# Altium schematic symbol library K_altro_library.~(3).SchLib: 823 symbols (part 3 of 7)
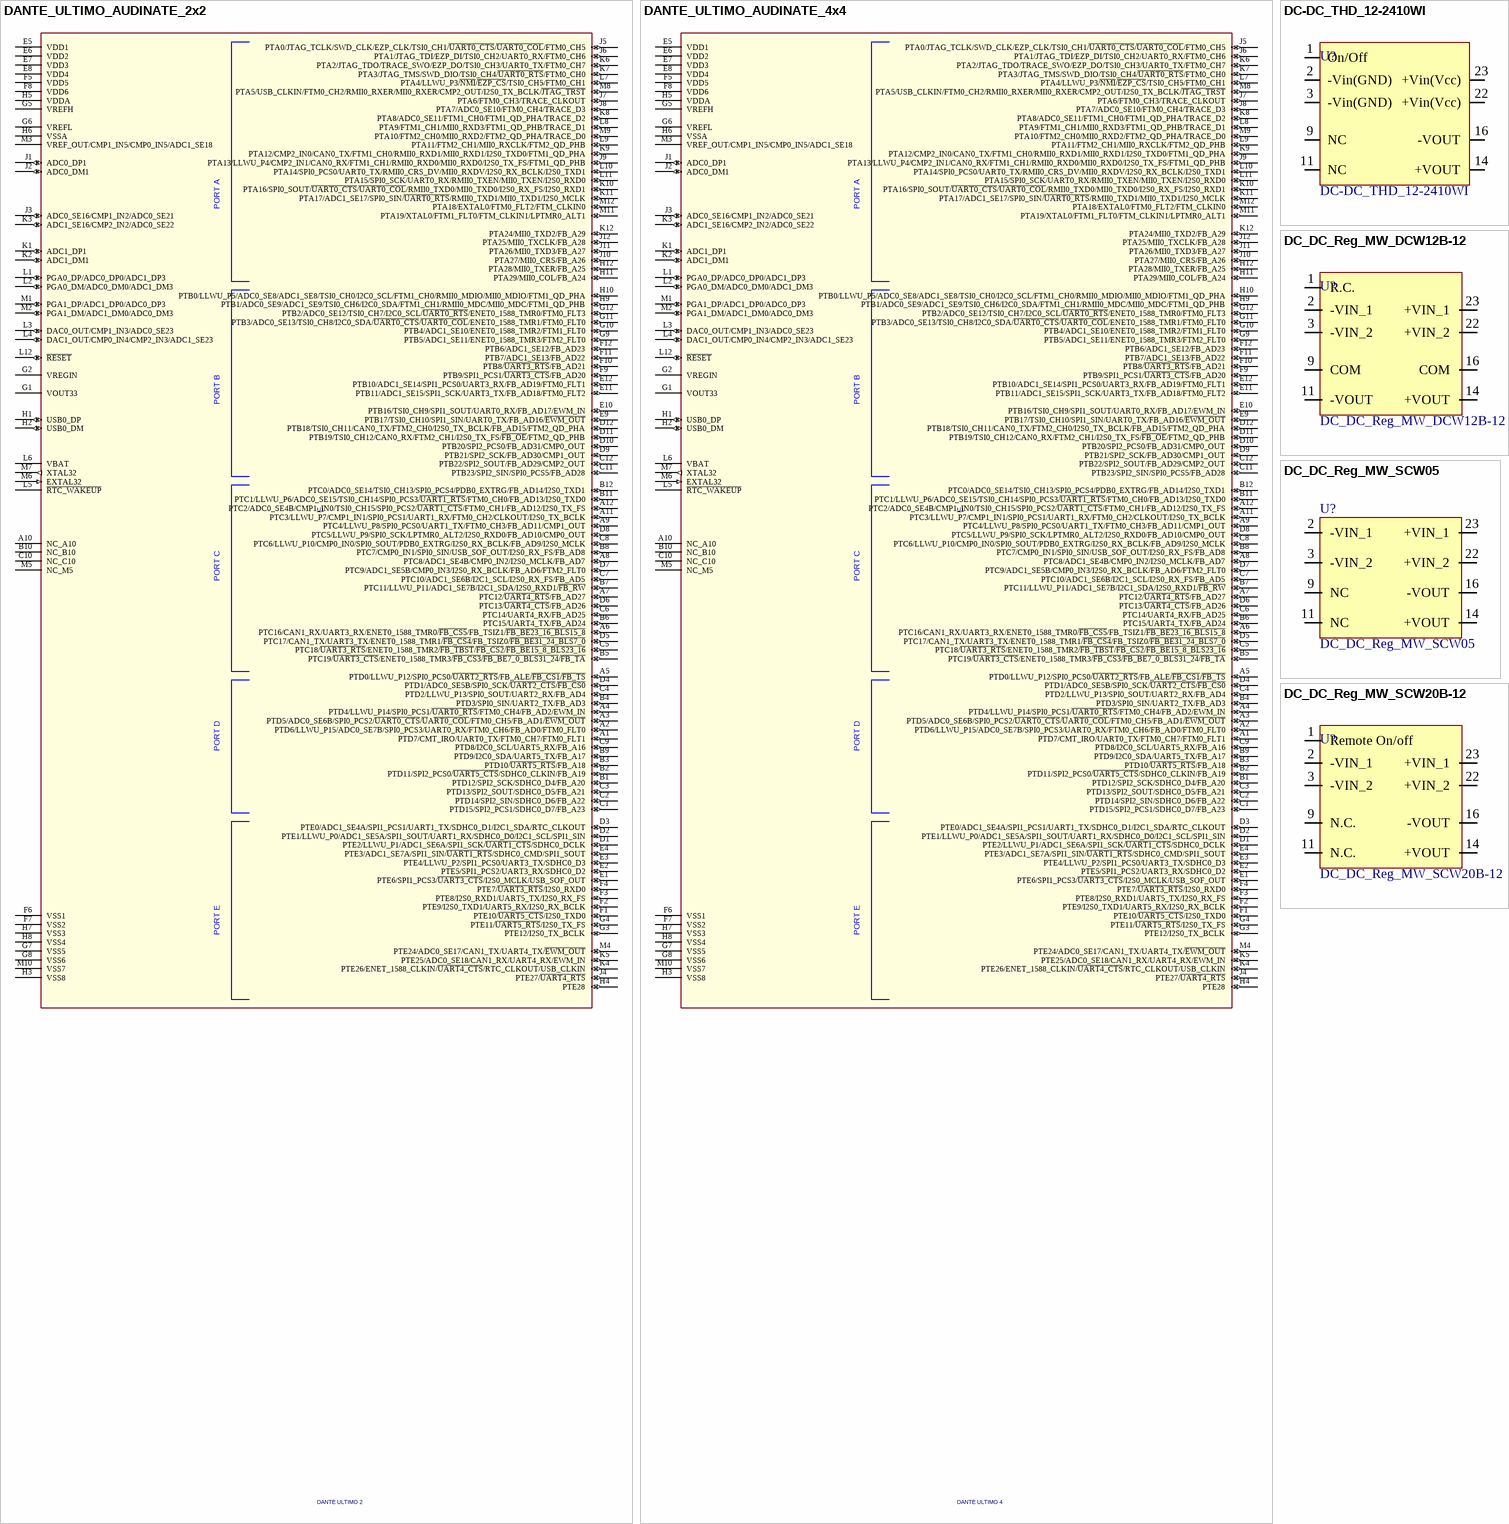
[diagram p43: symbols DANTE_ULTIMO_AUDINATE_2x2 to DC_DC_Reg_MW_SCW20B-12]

## DANTE_ULTIMO_AUDINATE_4x4
designator U1, comment DANTE ULTIMO 4
AUDINATE DANTE ULTIMO 4; Costo: 17; HPcode: 'ICULTIMO4x4 da codificare!; Aggiornato: S; ContoLavoro: 1
footprint FBGA144_mod (144-Ball FineLine Ball Grid Array (FBGA144))
pins: A1 PTD7/CMT_IRO/UART0_TX/FTM0_CH7/FTM0_FLT1 (io), A2 PTD6/LLWU_P15/ADC0_SE7B/SPI0_PCS3/UART0_RX/FTM0_CH6/FB_AD0/FTM0_FLT0 (io), A3 PTD5/ADC0_SE6B/SPI0_PCS2/~{UART0_CTS}/~{U}A~{RT0_COL}/FTM0_CH5/FB_AD1/~{EWM_OUT} (io), A4 PTD4/LLWU_P14/SPI0_PCS1/~{UART0_RTS}/FTM0_CH4/FB_AD2/EWM_IN (io), A5 PTD0/LLWU_P12/SPI0_PCS0/~{UART2_RTS}/FB_ALE/~{FB_CS1}/~{FB_TS} (io), A6 PTC16/CAN1_RX/UART3_RX/ENET0_1588_TMR0/~{FB_CS5}/FB_TSIZ1/~{FB_BE23_16_BLS15_8} (io), A7 PTC12/~{UART4_RTS}/FB_AD27 (io), A8 PTC8/ADC1_SE4B/CMP0_IN2/I2S0_MCLK/FB_AD7 (io), A9 PTC4/LLWU_P8/SPI0_PCS0/UART1_TX/FTM0_CH3/FB_AD11/CMP1_OUT (io), A10 NC_A10, A11 PTC3/LLWU_P7/CMP1_IN1/SPI0_PCS1/UART1_RX/FTM0_CH2/CLKOUT/I2S0_TX_BCLK (io), A12 PTC2/ADC0_SE4B/CMP1_IN0/TSI0_CH15/SPI0_PCS2/~{UART1_CTS}/FTM0_CH1/FB_AD12/I2S0_TX_FS (io), B1 PTD12/SPI2_SCK/SDHC0_D4/FB_A20 (io), B2 PTD11/SPI2_PCS0/~{UART5_CTS}/SDHC0_CLKIN/FB_A19 (io), B3 PTD10/~{UART5_RTS}/FB_A18 (io), B4 PTD3/SPI0_SIN/UART2_TX/FB_AD3 (io), B5 PTC19/~{UART3_CTS}/ENET0_1588_TMR3/~{FB_CS3}/~{FB_BE7_0_BLS31_24}/~{FB_TA} (io), B6 PTC15/UART4_TX/FB_AD24 (io), B7 PTC11/LLWU_P11/ADC1_SE7B/I2C1_SDA/I2S0_RXD1/~{FB_RW} (io), B8 PTC7/CMP0_IN1/SPI0_SIN/USB_SOF_OUT/I2S0_RX_FS/FB_AD8 (io), B9 PTD9/I2C0_SDA/UART5_TX/FB_A17 (io), B10 NC_B10, B11 PTC1/LLWU_P6/ADC0_SE15/TSI0_CH14/SPI0_PCS3/~{UART1_RTS}/FTM0_CH0/FB_AD13/I2S0_TXD0 (io), B12 PTC0/ADC0_SE14/TSI0_CH13/SPI0_PCS4/PDB0_EXTRG/FB_AD14/I2S0_TXD1 (io), C1 PTD15/SPI2_PCS1/SDHC0_D7/FB_A23 (io), C2 PTD14/SPI2_SIN/SDHC0_D6/FB_A22 (io), C3 PTD13/SPI2_SOUT/SDHC0_D5/FB_A21 (io), C4 PTD2/LLWU_P13/SPI0_SOUT/UART2_RX/FB_AD4 (io), C5 PTC18/~{UART3_RTS}/ENET0_1588_TMR2/~{FB_TBST}/~{FB_CS2}/~{FB_BE15_8_BLS23_16} (io), C6 PTC14/UART4_RX/FB_AD25 (io), C7 PTC10/ADC1_SE6B/I2C1_SCL/I2S0_RX_FS/FB_AD5 (io), C8 PTC6/LLWU_P10/CMP0_IN0/SPI0_SOUT/PDB0_EXTRG/I2S0_RX_BCLK/FB_AD9/I2S0_MCLK (io), C9 PTD8/I2C0_SCL/UART5_RX/FB_A16 (io), C10 NC_C10, C11 PTB23/SPI2_SIN/SPI0_PCS5/FB_AD28 (io), C12 PTB22/SPI2_SOUT/FB_AD29/CMP2_OUT (io), D1 PTE2/LLWU_P1/ADC1_SE6A/SPI1_SCK/~{UART1_CTS}/SDHC0_DCLK (io), D2 PTE1/LLWU_P0/ADC1_SE5A/SPI1_SOUT/UART1_RX/SDHC0_D0/I2C1_SCL/SPI1_SIN (io), D3 PTE0/ADC1_SE4A/SPI1_PCS1/UART1_TX/SDHC0_D1/I2C1_SDA/RTC_CLKOUT (io), D4 PTD1/ADC0_SE5B/SPI0_SCK/~{UART2_CTS}/~{FB_CS0} (io), D5 PTC17/CAN1_TX/UART3_TX/ENET0_1588_TMR1/~{FB_CS4}/FB_TSIZ0/~{FB_BE31_24_BLS7_0} (io), D6 PTC13/~{UART4_CTS}/FB_AD26 (io), D7 PTC9/ADC1_SE5B/CMP0_IN3/I2S0_RX_BCLK/FB_AD6/FTM2_FLT0 (io), D8 PTC5/LLWU_P9/SPI0_SCK/LPTMR0_ALT2/I2S0_RXD0/FB_AD10/CMP0_OUT (io), D9 PTB21/SPI2_SCK/FB_AD30/CMP1_OUT (io), D10 PTB20/SPI2_PCS0/FB_AD31/CMP0_OUT (io), D11 PTB19/TSI0_CH12/CAN0_RX/FTM2_CH1/I2S0_TX_FS/~{FB_OE}/FTM2_QD_PHB (io), D12 PTB18/TSI0_CH11/CAN0_TX/FTM2_CH0/I2S0_TX_BCLK/FB_AD15/FTM2_QD_PHA (io), E1 PTE6/SPI1_PCS3/~{UART3_CTS}/I2S0_MCLK/USB_SOF_OUT (io), E2 PTE5/SPI1_PCS2/UART3_RX/SDHC0_D2 (io), E3 PTE4/LLWU_P2/SPI1_PCS0/UART3_TX/SDHC0_D3 (io), E4 PTE3/ADC1_SE7A/SPI1_SIN/~{UART1_RTS}/SDHC0_CMD/SPI1_SOUT (io), E5 VDD1 (power), E6 VDD2 (power), E7 VDD3 (power), E8 VDD4 (power), E9 PTB17/TSI0_CH10/SPI1_SIN/UART0_TX/FB_AD16/~{EWM_OUT} (io), E10 PTB16/TSI0_CH9/SPI1_SOUT/UART0_RX/FB_AD17/EWM_IN (io), E11 PTB11/ADC1_SE15/SPI1_SCK/UART3_TX/FB_AD18/FTM0_FLT2 (io), E12 PTB10/ADC1_SE14/SPI1_PCS0/UART3_RX/FB_AD19/FTM0_FLT1 (io), F1 PTE10/~{UART5_CTS}/I2S0_TXD0 (io), F2 PTE9/I2S0_TXD1/UART5_RX/I2S0_RX_BCLK (io), F3 PTE8/I2S0_RXD1/UART5_TX/I2S0_RX_FS (io), F4 PTE7/~{UART3_RTS}/I2S0_RXD0 (io), F5 VDD5 (power), F6 VSS1 (power), F7 VSS2 (power), F8 VDD6 (power), F9 PTB9/SPI1_PCS1/~{UART3_CTS}/FB_AD20 (io), F10 PTB8/~{UART3_RTS}/FB_AD21 (io), F11 PTB7/ADC1_SE13/FB_AD22 (io), F12 PTB6/ADC1_SE12/FB_AD23 (io), G1 VOUT33 (power), G2 VREGIN (power), G3 PTE12/I2S0_TX_BCLK (io), G4 PTE11/~{UART5_RTS}/I2S0_TX_FS (io), G5 VREFH (power), G6 VREFL (power), G7 VSS5 (power), G8 VSS6 (power), G9 PTB5/ADC1_SE11/ENET0_1588_TMR3/FTM2_FLT0 (io), G10 PTB4/ADC1_SE10/ENET0_1588_TMR2/FTM1_FLT0 (io), G11 PTB3/ADC0_SE13/TSI0_CH8/I2C0_SDA/~{UART0_CTS}/~{UART0_COL}/ENET0_1588_TMR1/FTM0_FLT0 (io), G12 PTB2/ADC0_SE12/TSI0_CH7/I2C0_SCL/~{UART0_RTS}/ENET0_1588_TMR0/FTM0_FLT3 (io), H1 USB0_DP (io), H2 USB0_DM (io), H3 VSS8 (power), H4 PTE28 (io), H5 VDDA (power), H6 VSSA (power), H7 VSS3 (power), H8 VSS4 (power), H9 PTB1/ADC0_SE9/ADC1_SE9/TSI0_CH6/I2C0_SDA/FTM1_CH1/RMII0_MDC/MII0_MDC/FTM1_QD_PHB (io), H10 PTB0/LLWU_P5/ADC0_SE8/ADC1_SE8/TSI0_CH0/I2C0_SCL/FTM1_CH0/RMII0_MDIO/MII0_MDIO/FTM1_QD_PHA (io), H11 PTA29/MII0_COL/FB_A24 (io), H12 PTA28/MII0_TXER/FB_A25 (io), J1 ADC0_DP1 (io), J2 ADC0_DM1 (io), J3 ADC0_SE16/CMP1_IN2/ADC0_SE21 (io), J4 PTE27/~{UART4_RTS} (io), J5 PTA0/JTAG_TCLK/SWD_CLK/EZP_CLK/TSI0_CH1/~{UART0_CTS}/~{UART0_COL}/FTM0_CH5 (io), J6 PTA1/JTAG_TDI/EZP_DI/TSI0_CH2/UART0_RX/FTM0_CH6 (io), J7 PTA6/FTM0_CH3/TRACE_CLKOUT (io), J8 PTA7/ADC0_SE10/FTM0_CH4/TRACE_D3 (io), J9 PTA13/LLWU_P4/CMP2_IN1/CAN0_RX/FTM1_CH1/RMII0_RXD0/MII0_RXD0/I2S0_TX_FS/FTM1_QD_PHB (io), J10 PTA27/MII0_CRS/FB_A26 (io), J11 PTA26/MII0_TXD3/FB_A27 (io), J12 PTA25/MII0_TXCLK/FB_A28 (io), K1 ADC1_DP1 (io), K2 ADC1_DM1 (io), K3 ADC1_SE16/CMP2_IN2/ADC0_SE22 (io), K4 PTE26/ENET_1588_CLKIN/~{UART4_CTS}/RTC_CLKOUT/USB_CLKIN (io), K5 PTE25/ADC0_SE18/CAN1_RX/UART4_RX/EWM_IN (io), K6 PTA2/JTAG_TDO/TRACE_SWO/EZP_DO/TSI0_CH3/UART0_TX/FTM0_CH7 (io), K7 PTA3/JTAG_TMS/SWD_DIO/TSI0_CH4/~{UART0_RTS}/FTM0_CH0 (io), K8 PTA8/ADC0_SE11/FTM1_CH0/FTM1_QD_PHA/TRACE_D2 (io), K9 PTA12/CMP2_IN0/CAN0_TX/FTM1_CH0/RMII0_RXD1/MII0_RXD1/I2S0_TXD0/FTM1_QD_PHA (io), K10 PTA16/SPI0_SOUT/~{UART0_CTS}/~{UART0_COL}/RMII0_TXD0/MII0_TXD0/I2S0_RX_FS/I2S0_RXD1 (io), K11 PTA17/ADC1_SE17/SPI0_SIN/~{UART0_RTS}/RMII0_TXD1/MII0_TXD1/I2S0_MCLK (io), K12 PTA24/MII0_TXD2/FB_A29 (io), L1 PGA0_DP/ADC0_DP0/ADC1_DP3 (io), L2 PGA0_DM/ADC0_DM0/ADC1_DM3 (io), L3 DAC0_OUT/CMP1_IN3/ADC0_SE23 (io), L4 DAC1_OUT/CMP0_IN4/CMP2_IN3/ADC1_SE23 (io), L5 ~{RTC_WAKEUP}, L6 VBAT (power), L7 PTA4/LLWU_P3/~{NMI}/~{EZP_CS}/TSI0_CH5/FTM0_CH1 (io), L8 PTA9/FTM1_CH1/MII0_RXD3/FTM1_QD_PHB/TRACE_D1 (io), L9 PTA11/FTM2_CH1/MII0_RXCLK/FTM2_QD_PHB (io), L10 PTA14/SPI0_PCS0/UART0_TX/RMII0_CRS_DV/MII0_RXDV/I2S0_RX_BCLK/I2S0_TXD1 (io), L11 PTA15/SPI0_SCK/UART0_RX/RMII0_TXEN/MII0_TXEN/I2S0_RXD0 (io), L12 ~{RESET} (io), M1 PGA1_DP/ADC1_DP0/ADC0_DP3 (io), M2 PGA1_DM/ADC1_DM0/ADC0_DM3 (io), M3 VREF_OUT/CMP1_IN5/CMP0_IN5/ADC1_SE18 (power), M4 PTE24/ADC0_SE17/CAN1_TX/UART4_TX/~{EWM_OUT} (io), M5 NC_M5, M6 EXTAL32 (in), M7 XTAL32 (out), M8 PTA5/USB_CLKIN/FTM0_CH2/RMII0_RXER/MII0_RXER/CMP2_OUT/I2S0_TX_BCLK/~{JTAG_TRST} (io), M9 PTA10/FTM2_CH0/MII0_RXD2/FTM2_QD_PHA/TRACE_D0 (io), M10 VSS7 (power), M11 PTA19/XTAL0/FTM1_FLT0/FTM_CLKIN1/LPTMR0_ALT1 (io), M12 PTA18/EXTAL0/FTM0_FLT2/FTM_CLKIN0 (io)

## DC-DC_THD_12-2410WI
designator U?
Costo: 0; Aggiornato: NO
footprint DC-DC_THD_12-2410WI (Footprint not found)
pins: 1 On/Off, 2 -Vin(GND), 3 -Vin(GND), 9 NC, 11 NC, 14 +VOUT, 16 -VOUT, 22 +Vin(Vcc), 23 +Vin(Vcc)

## DC_DC_Reg_MW_DCW12B-12
designator U?
Costo: 0; Aggiornato: NO
footprint DC_DC_Reg_MW_SCW20_DCW12
pins: 1 R.C., 2 -VIN_1, 3 -VIN_2, 9 COM, 11 -VOUT, 14 +VOUT, 16 COM, 22 +VIN_2, 23 +VIN_1

## DC_DC_Reg_MW_SCW05
designator U?
HPcode: ALISCW05B12; Costo: 0; Aggiornato: NO
footprint DC_DC_Reg_MW_SCW05
pins: 2 -VIN_1, 3 -VIN_2, 9 NC, 11 NC, 14 +VOUT, 16 -VOUT, 22 +VIN_2, 23 +VIN_1

## DC_DC_Reg_MW_SCW20B-12
designator U?
Costo: 0; Aggiornato: NO
footprint DC_DC_Reg_MW_SCW20_DCW12
pins: 1 Remote On/off, 2 -VIN_1, 3 -VIN_2, 9 N.C., 11 N.C., 14 +VOUT, 16 -VOUT, 22 +VIN_2, 23 +VIN_1

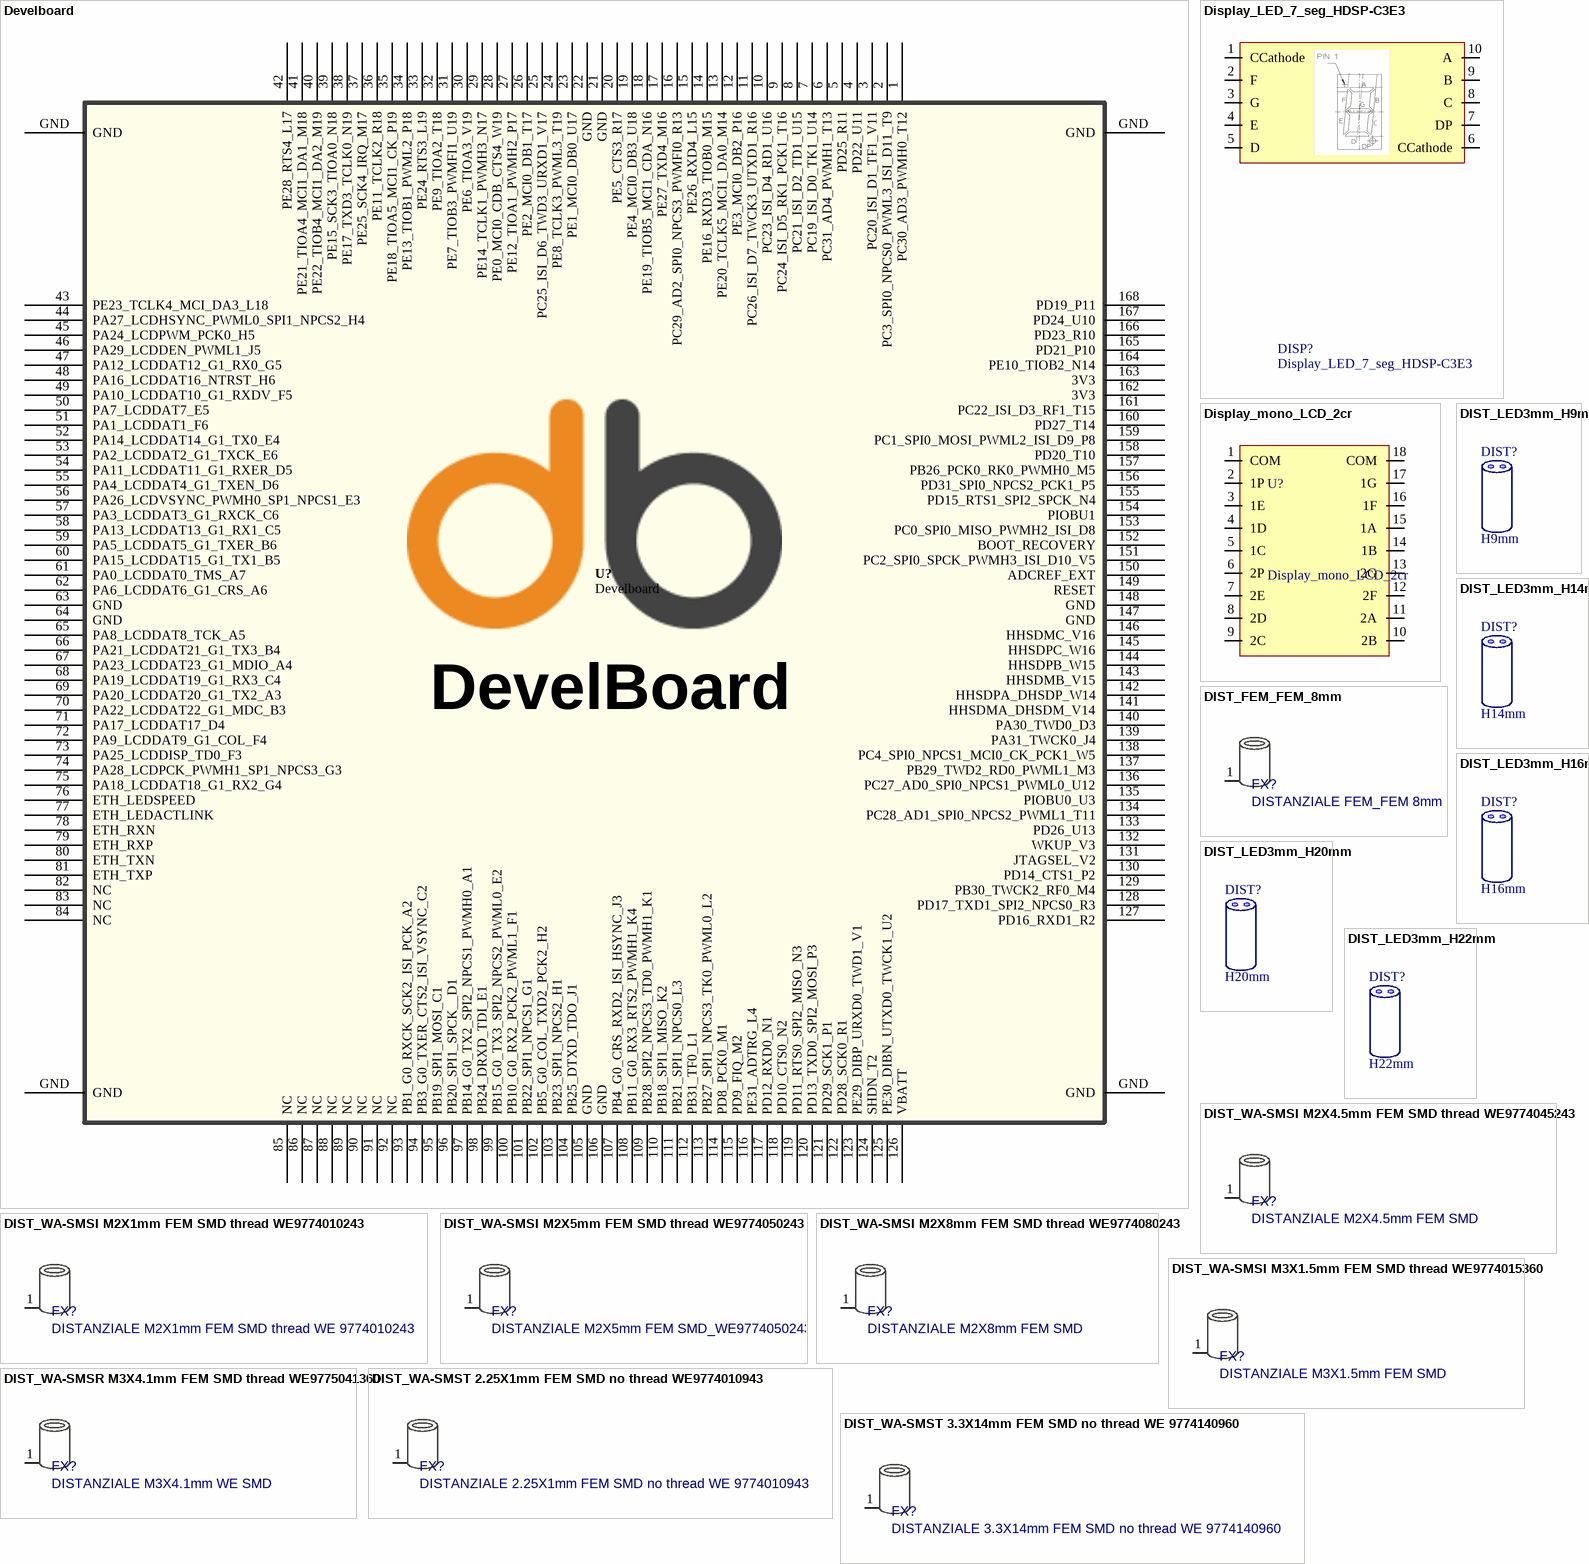
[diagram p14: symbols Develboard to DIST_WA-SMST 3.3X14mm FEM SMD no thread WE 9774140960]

## Develboard
designator U?
Aggiornato: NO; Costo: 0
footprint develboard_footprint
pins: 1 PC30_AD3_PWMH0_T12, 2 PC3_SPI0_NPCS0_PWML3_ISI_D11_T9, 3 PC20_ISI_D1_TF1_V11, 4 PD22_U11, 5 PD25_R11, 6 PC31_AD4_PWMH1_T13, 7 PC19_ISI_D0_TK1_U14, 8 PC21_ISI_D2_TD1_U15, 9 PC24_ISI_D5_RK1_PCK1_T16, 10 PC23_ISI_D4_RD1_U16, 11 PC26_ISI_D7_TWCK3_UTXD1_R16, 12 PE3_MCI0_DB2_P16, 13 PE20_TCLK5_MCI1_DA0_M14, 14 PE16_RXD3_TIOB0_M15, 15 PE26_RXD4_L15, 16 PC29_AD2_SPI0_NPCS3_PWMFI0_R13, 17 PE27_TXD4_M16, 18 PE19_TIOB5_MCI1_CDA_N16, 19 PE4_MCI0_DB3_U18, 20 PE5_CTS3_R17, 21 GND, 22 GND, 23 PE1_MCI0_DB0_U17, 24 PE8_TCLK3_PWML3_T19, 25 PC25_ISI_D6_TWD3_URXD1_V17, 26 PE2_MCI0_DB1_T17, 27 PE12_TIOA1_PWMH2_P17, 28 PE0_MCI0_CDB_CTS4_W19, 29 PE14_TCLK1_PWMH3_N17, 30 PE6_TIOA3_V19, 31 PE7_TIOB3_PWMFI1_U19, 32 PE9_TIOA2_T18, 33 PE24_RTS3_L19, 34 PE13_TIOB1_PWML2_P18, 35 PE18_TIOA5_MCI1_CK_P19, 36 PE11_TCLK2_R18, 37 PE25_SCK4_IRQ_M17, 38 PE17_TXD3_TCLK0_N19, 39 PE15_SCK3_TIOA0_N18, 40 PE22_TIOB4_MCI1_DA2_M19, 41 PE21_TIOA4_MCI1_DA1_M18, 42 PE28_RTS4_L17, 43 PE23_TCLK4_MCI_DA3_L18, 44 PA27_LCDHSYNC_PWML0_SPI1_NPCS2_H4, 45 PA24_LCDPWM_PCK0_H5, 46 PA29_LCDDEN_PWML1_J5, 47 PA12_LCDDAT12_G1_RX0_G5, 48 PA16_LCDDAT16_NTRST_H6, 49 PA10_LCDDAT10_G1_RXDV_F5, 50 PA7_LCDDAT7_E5, 51 PA1_LCDDAT1_F6, 52 PA14_LCDDAT14_G1_TX0_E4, 53 PA2_LCDDAT2_G1_TXCK_E6, 54 PA11_LCDDAT11_G1_RXER_D5, 55 PA4_LCDDAT4_G1_TXEN_D6, 56 PA26_LCDVSYNC_PWMH0_SP1_NPCS1_E3, 57 PA3_LCDDAT3_G1_RXCK_C6, 58 PA13_LCDDAT13_G1_RX1_C5, 59 PA5_LCDDAT5_G1_TXER_B6, 60 PA15_LCDDAT15_G1_TX1_B5, 61 PA0_LCDDAT0_TMS_A7, 62 PA6_LCDDAT6_G1_CRS_A6, 63 GND, 64 GND, 65 PA8_LCDDAT8_TCK_A5, 66 PA21_LCDDAT21_G1_TX3_B4, 67 PA23_LCDDAT23_G1_MDIO_A4, 68 PA19_LCDDAT19_G1_RX3_C4, 69 PA20_LCDDAT20_G1_TX2_A3, 70 PA22_LCDDAT22_G1_MDC_B3, 71 PA17_LCDDAT17_D4, 72 PA9_LCDDAT9_G1_COL_F4, 73 PA25_LCDDISP_TD0_F3, 74 PA28_LCDPCK_PWMH1_SP1_NPCS3_G3, 75 PA18_LCDDAT18_G1_RX2_G4, 76 ETH_LEDSPEED, 77 ETH_LEDACTLINK, 78 ETH_RXN, 79 ETH_RXP, 80 ETH_TXN, 81 ETH_TXP, 82 NC, 83 NC, 84 NC, 85 NC, 86 NC, 87 NC, 88 NC, 89 NC, 90 NC, 91 NC, 92 NC, 93 PB1_G0_RXCK_SCK2_ISI_PCK_A2, 94 PB3_G0_TXER_CTS2_ISI_VSYNC_C2, 95 PB19_SPI1_MOSI_C1, 96 PB20_SPI1_SPCK__D1, 97 PB14_G0_TX2_SPI2_NPCS1_PWMH0_A1, 98 PB24_DRXD_TDI_E1, 99 PB15_G0_TX3_SPI2_NPCS2_PWML0_E2, 100 PB10_G0_RX2_PCK2_PWML1_F1, 101 PB22_SPI1_NPCS1_G1, 102 PB5_G0_COL_TXD2_PCK2_H2, 103 PB23_SPI1_NPCS2_H1, 104 PB25_DTXD_TDO_J1, 105 GND, 106 GND, 107 PB4_G0_CRS_RXD2_ISI_HSYNC_J3, 108 PB11_G0_RX3_RTS2_PWMH1_K4, 109 PB28_SPI2_NPCS3_TD0_PWMH1_K1, 110 PB18_SPI1_MISO_K2, 111 PB21_SPI1_NPCS0_L3, 112 PB31_TF0_L1, 113 PB27_SPI1_NPCS3_TK0_PWML0_L2, 114 PD8_PCK0_M1, 115 PD9_FIQ_M2, 116 PE31_ADTRG_L4, 117 PD12_RXD0_N1, 118 PD10_CTS0_N2, 119 PD11_RTS0_SPI2_MISO_N3, 120 PD13_TXD0_SPI2_MOSI_P3, 121 PD29_SCK1_P1, 122 PD28_SCK0_R1, 123 PE29_DIBP_URXD0_TWD1_V1, 124 SHDN_T2, 125 PE30_DIBN_UTXD0_TWCK1_U2, 126 VBATT, 127 PD16_RXD1_R2, 128 PD17_TXD1_SPI2_NPCS0_R3, 129 PB30_TWCK2_RF0_M4, 130 PD14_CTS1_P2, 131 JTAGSEL_V2, 132 WKUP_V3, 133 PD26_U13, 134 PC28_AD1_SPI0_NPCS2_PWML1_T11, 135 PIOBU0_U3, 136 PC27_AD0_SPI0_NPCS1_PWML0_U12, 137 PB29_TWD2_RD0_PWML1_M3, 138 PC4_SPI0_NPCS1_MCI0_CK_PCK1_W5, 139 PA31_TWCK0_J4, 140 PA30_TWD0_D3, 141 HHSDMA_DHSDM_V14, 142 HHSDPA_DHSDP_W14, 143 HHSDMB_V15, 144 HHSDPB_W15, 145 HHSDPC_W16, 146 HHSDMC_V16, 147 GND, 148 GND, 149 RESET, 150 ADCREF_EXT, 151 PC2_SPI0_SPCK_PWMH3_ISI_D10_V5, 152 BOOT_RECOVERY, 153 PC0_SPI0_MISO_PWMH2_ISI_D8, 154 PIOBU1, 155 PD15_RTS1_SPI2_SPCK_N4, 156 PD31_SPI0_NPCS2_PCK1_P5, 157 PB26_PCK0_RK0_PWMH0_M5, 158 PD20_T10, 159 PC1_SPI0_MOSI_PWML2_ISI_D9_P8, 160 PD27_T14, 161 PC22_ISI_D3_RF1_T15, 162 3V3, 163 3V3, 164 PE10_TIOB2_N14, 165 PD21_P10, 166 PD23_R10, 167 PD24_U10, 168 PD19_P11, GND, GND, GND, GND

## Display_LED_7_seg_HDSP-C3E3
designator DISP?
Aggiornato: n; Costo: 0
footprint Display_LED_7_seg_HDSP-C3E3 (Display_LED_7_seg HDSP-C3E3)
pins: 1 CCathode "Common Cathode", 2 F, 3 G, 4 E, 5 D, 6 CCathode "Common Cathode", 7 DP, 8 C, 9 B, 10 A

## Display_mono_LCD_2cr
designator U?
Costo: 5; Aggiornato: n; ContoLavoro: 0
footprint DISPLAY_LCD_RS215-6442
pins: 1 COM, 2 1P, 3 1E, 4 1D, 5 1C, 6 2P, 7 2E, 8 2D, 9 2C, 10 2B, 11 2A, 12 2F, 13 2G, 14 1B, 15 1A, 16 1F, 17 1G, 18 COM

## DIST_FEM_FEM_8mm
designator FX?, comment DISTANZIALE FEM_FEM 8mm
Hpcode: DISTFFM3H08; Costo: 0,06; Aggiornato: S; ContoLavoro: 1
footprint SCREW_M3_ELECTRIC
pins: 1

## DIST_LED3mm_H9mm
designator DIST?, comment H9mm  (mechanical)
DISTANZIALE PER LED 2PIN 3mm H9mm; Costo: 0,05; Aggiornato: s; Detail: COSTO IPOTIZZATO; ContoLavoro: 0
pins: 1 hidden
1 alternate drawing of the same symbol

## DIST_LED3mm_H14mm
designator DIST?, comment H14mm  (mechanical)
DISTANZIALE PER LED 2PIN 3mm H14mm; Costo: 0,05; Aggiornato: s; Detail: COSTO IPOTIZZATO; ContoLavoro: 0
pins: 1 hidden
1 alternate drawing of the same symbol

## DIST_LED3mm_H16mm
designator DIST?, comment H16mm  (mechanical)
DISTANZIALE PER LED 2PIN 3mm H16mm; Costo: 0,05; Aggiornato: NO; Detail: COSTO IPOTIZZATO; ContoLavoro: 0
pins: 1 hidden
1 alternate drawing of the same symbol

## DIST_LED3mm_H20mm
designator DIST?, comment H20mm  (mechanical)
DISTANZIALE PER LED 2PIN 3mm H20mm; Costo: 0,05; Aggiornato: NO; Detail: COSTO IPOTIZZATO; ContoLavoro: 0
pins: 1 hidden
1 alternate drawing of the same symbol

## DIST_LED3mm_H22mm
designator DIST?, comment H22mm  (mechanical)
DISTANZIALE PER LED 2PIN 3mm H22mm; Costo: 0,05; Aggiornato: NO; Detail: COSTO IPOTIZZATO; ContoLavoro: 0
pins: 1 hidden
1 alternate drawing of the same symbol

## DIST_WA-SMSI M2X1mm FEM SMD thread WE9774010243
designator FX?, comment DISTANZIALE M2X1mm FEM SMD thread WE 9774010243
Detail: 0,06€ 1000pz WE offerta A18IT013140.pdf; Costo: 0,06; Aggiornato: S; ContoLavoro: 0
footprint Distanziale 2.25x1mm WE9774010943
pins: 1

## DIST_WA-SMSI M2X4.5mm FEM SMD thread WE9774045243
designator FX?, comment DISTANZIALE M2X4.5mm FEM SMD
Detail: 0; Aggiornato: NO
footprint Distanziale M2x4.5mm WE9774045243
pins: 1

## DIST_WA-SMSI M2X5mm FEM SMD thread WE9774050243
designator FX?, comment DISTANZIALE M2X5mm FEM SMD_WE9774050243
DISTANZIALE M2X5mm FEM SMD; Detail: € Wurth Pz> 100; Hpcode: DISTF2X5SMD; Costo: 0,15; Aggiornato: S; ContoLavoro: 0
footprint Distanziale M2x5mm WE9774050243
pins: 1

## DIST_WA-SMSI M2X8mm FEM SMD thread WE9774080243
designator FX?, comment DISTANZIALE M2X8mm FEM SMD
Detail: € Wurth Pz> 100; Costo: 0; Aggiornato: N
footprint Distanziale M2x8mm WE9774080243
pins: 1

## DIST_WA-SMSI M3X1.5mm FEM SMD thread WE9774015360
designator FX?, comment DISTANZIALE M3X1.5mm FEM SMD
Detail: 9774015360 0,115€ Wurth Pz3000 , 9774015360R 0,190 Wurth Pz3600; Costo: 0,19; Aggiornato: S; ContoLavoro: 0
footprint Distanziale M3x1.5mm WE9774015360
pins: 1

## DIST_WA-SMSR M3X4.1mm FEM SMD thread WE9775041360
designator FX?, comment DISTANZIALE M3X4.1mm WE SMD
DISTANZIALE SMD M3X4.1mm internal thread WE; Detail: € Wurth Pz> 100; Hpcode: DISTF2X5SMD; Costo: 0,15; Aggiornato: S; ContoLavoro: 0
footprint DISTANZIALE SMD M3x4.1 WE 9775041360
pins: 1

## DIST_WA-SMST 2.25X1mm FEM SMD no thread WE9774010943
designator FX?, comment DISTANZIALE 2.25X1mm FEM SMD no thread WE 9774010943
DISTANZIALE 2.25X1mm FEM SMD; Costo: 0; Aggiornato: N
footprint Distanziale 2.25x1mm WE9774010943
pins: 1

## DIST_WA-SMST 3.3X14mm FEM SMD no thread WE 9774140960
designator FX?, comment DISTANZIALE 3.3X14mm FEM SMD no thread WE 9774140960
DISTANZIALE 3.3X14mm FEM SMD; Detail: da quotare credo 0,195 indicativo; Costo: 0,195; Aggiornato: S; ContoLavoro: 0
footprint Distanziale 3.3x14mm WE9774140960
pins: 1

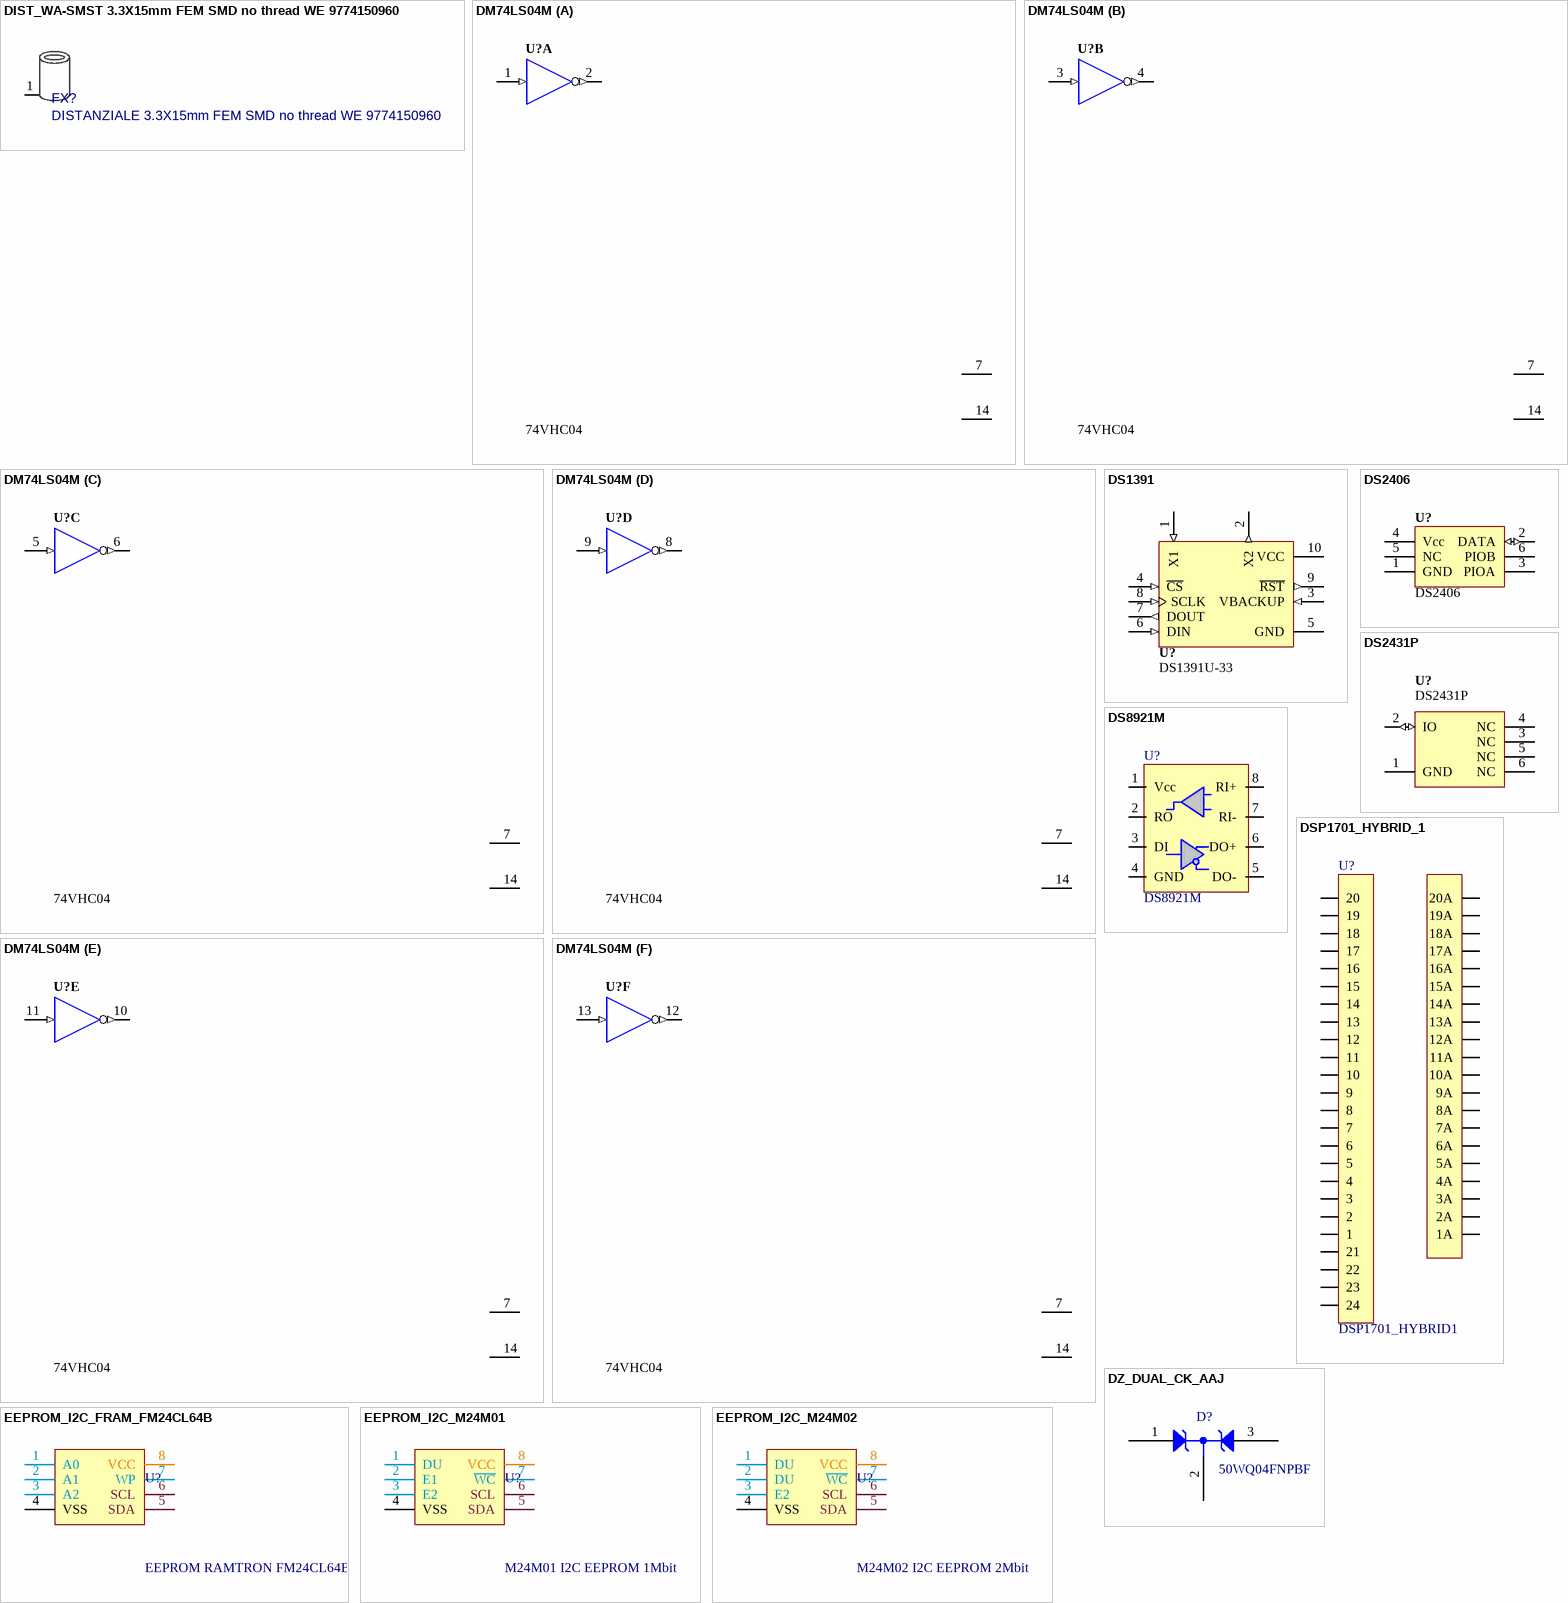
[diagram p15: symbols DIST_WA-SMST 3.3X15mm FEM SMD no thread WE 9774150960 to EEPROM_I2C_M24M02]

## DIST_WA-SMST 3.3X15mm FEM SMD no thread WE 9774150960
designator FX?, comment DISTANZIALE 3.3X15mm FEM SMD no thread WE 9774150960
DISTANZIALE 3.3X15mm FEM SMD; Detail: 0,195€ WE Pz>3000 Offerta A19IT023595; Costo: 0,195; Aggiornato: S; ContoLavoro: 0
footprint Distanziale 3.3x15mm WE9774150960
pins: 1

## DM74LS04M
designator U?, comment 74VHC04
HEX Inverter; Aggiornato: NO; Costo: 0
footprint TSSOP14
pins on every part: 7 GND (power), 14 VCC (power)
part A pins: 1 A (in), 2 Y (out)
part B pins: 3 A (in), 4 Y (out)
part C pins: 5 A (in), 6 Y (out)
part D pins: 8 Y (out), 9 A (in)
part E pins: 10 Y (out), 11 A (in)
part F pins: 12 Y (out), 13 A (in)

## DS1391
designator U?, comment DS1391U-33
DS1391U-33, SPI Real-Time Clock with Trickle Charger, 3.3V, 10-Pin uMax/uSOP; Aggiornato: NO; Costo: 0
footprint SSOP50P490-10
pins: 1 X1 (in) "Internal Oscillator Input. Or connection to external 32.768kHz oscillator.", 2 X2 (out) "Internal Oscillator Output. Float if external oscillator connected to pin X1.", 3 VBACKUP (in) "DC Backup Power Input for Primary Cell.", 4 ~{CS} (in) "SPI Chip-Select Input. Used to select or deselect the device.", 5 GND (power) "Ground", 6 DIN (in) "SPI Data Input. Used to shift address and data into the device.", 7 DOUT (out) "SPI Data Output. Data is output when the device is in read mode.", 8 SCLK (in) "Serial Clock Input. Used to control the timing of data in and out.", 9 ~{RST} (out) "Reset", 10 VCC (power) "DC Power Pin for Primary Power Supply."

## DS2406
designator U?
Dual Addressable Switch Plus 1KB Memory; Bit Width: Bits; Supply Voltage: mV; Aggiornato: NO; Costo: 0
footprint TSOC6
pins: 1 GND (power), 2 DATA (io), 3 PIOA (oc), 4 Vcc, 5 NC, 6 PIOB

## DS2431P
designator U?
EEPROM, 1-wire, 1024-bit, Surface Mount; Bit Width: Bits; Supply Voltage: 2.8 to 5.25V; Aggiornato: NO; Costo: 0
footprint DSO-C6-D4
pins: 1 GND (power), 2 IO (io), 3 NC, 4 NC, 5 NC, 6 NC

## DS8921M
designator U?
Detail: $0,549 >1000pz TI; Costo: 0,7; Aggiornato: S; ContoLavoro: 0
footprint SO8
pins: 1 Vcc, 2 RO, 3 DI, 4 GND, 5 DO-, 6 DO+, 7 RI-, 8 RI+

## DSP1701_HYBRID_1
designator U?, comment DSP1701_HYBRID1
Aggiornato: NO; Costo: 0
footprint DSP1701_HYBRID1 (Footprint not found)
pins: 1, 1A, 2, 2A, 3, 3A, 4, 4A, 5, 5A, 6, 6A, 7, 7A, 8, 8A, 9, 9A, 10, 10A, 11, 11A, 12, 12A, 13, 13A, 14, 14A, 15, 15A, 16, 16A, 17, 17A, 18, 18A, 19, 19A, 20, 20A, 21, 22, 23, 24

## DZ_DUAL_CK_AAJ
designator D?, comment 50WQ04FNPBF
Costo: 0,626; Aggiornato: NO; ContoLavoro: 0
footprint DPACK_TO252
pins: 0 hidden, 1, 2, 3

## EEPROM_I2C_FRAM_FM24CL64B
designator U?, comment EEPROM RAMTRON FM24CL64B
I2C EEPROM 256KBIT 400KHZ  8SOIC; HPcode: ICFM24CL64BG; Aggiornato: S; Costo: 0,59; ContoLavoro: 1
footprint SO8
pins: 1 A0, 2 A1, 3 A2, 4 VSS, 5 SDA, 6 SCL, 7 WP, 8 VCC

## EEPROM_I2C_M24M01
designator U?, comment M24M01 I2C EEPROM 1Mbit
Detail: 0,635€ RS pz>126; HPcode: ICM24M01; Aggiornato: S; Costo: 0,635; ContoLavoro: 0
footprint SO8
pins: 1 DU, 2 E1, 3 E2, 4 VSS, 5 SDA, 6 SCL, 7 ~{WC}, 8 VCC

## EEPROM_I2C_M24M02
designator U?, comment M24M02 I2C EEPROM 2Mbit
Detail: 1,79€ RS pz>500, 0,96€ Avnet pz>2500; HPcode: ICM24M02; Aggiornato: S; Costo: 0,96; ContoLavoro: 1
footprint SO8
pins: 1 DU, 2 DU, 3 E2, 4 VSS, 5 SDA, 6 SCL, 7 ~{WC}, 8 VCC

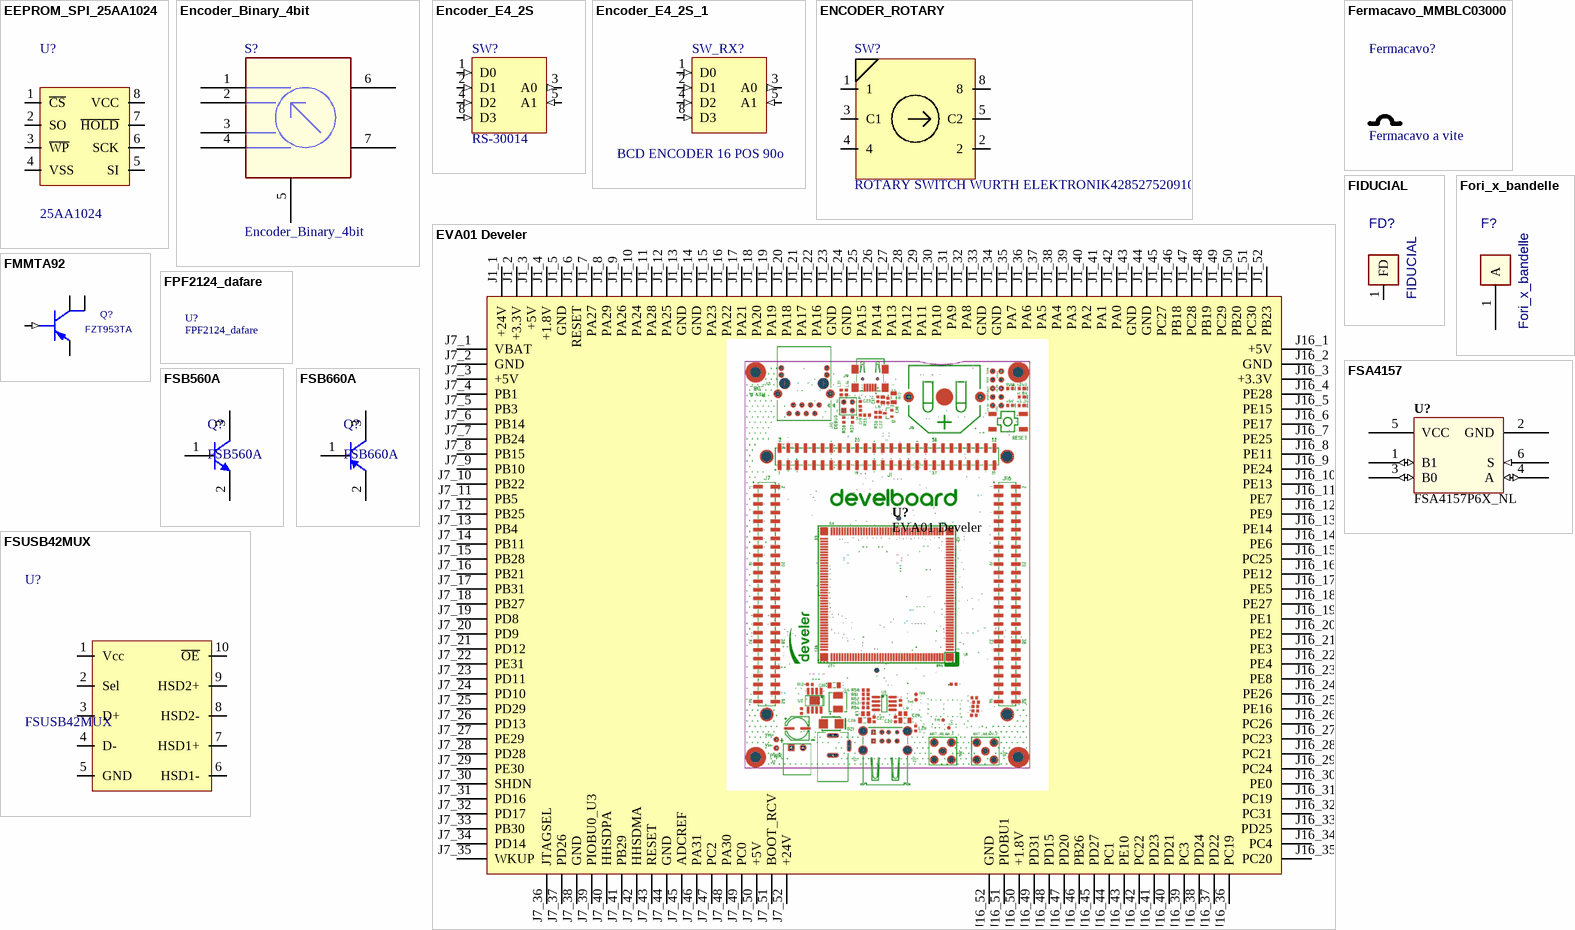
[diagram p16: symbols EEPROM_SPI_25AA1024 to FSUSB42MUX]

## EEPROM_SPI_25AA1024
designator U?, comment 25AA1024
25AA1024 1 Mbit SPI Bus Serial EEPROM; Costo: 0,39; Detail: € RS pz>40; Aggiornato: S; ContoLavoro: 0
footprint SOIJ8_25AA1024_SM
pins: 1 ~{CS}, 2 SO, 3 ~{WP}, 4 VSS, 5 SI, 6 SCK, 7 ~{HOLD}, 8 VCC

## Encoder_Binary_4bit
designator S?
Hpcode: ENCRBIN5CVA20; Aggiornato: NO; Costo: 0
footprint ENCODER REB161PVB_NOBLE
footprint ENCODER4BIT_RE200F
pins: 1, 2, 3 4, 4 8, 5 COM, 6 COM1, 7 COM2

## Encoder_E4_2S
designator SW?, comment RS-30014
4- to 2-Bit Priority Encoder, Single Pin Version; Aggiornato: NO; Costo: 0
footprint ENCODER_RS3XX
pins: 1 D0 (in), 2 D1 (in), 3 A0 (out), 4 D2 (in), 5 A1 (in), 8 D3 (in)

## Encoder_E4_2S_1
designator SW_RX?, comment BCD ENCODER 16 POS 90o
4- to 2-Bit Priority Encoder, Single Pin Version; Aggiornato: NO; Costo: 0
footprint ENCODER_RR3XX
pins: 1 D0 (in), 2 D1 (in), 3 A0 (out), 4 D2 (in), 5 A1 (in), 8 D3 (in)

## ENCODER_ROTARY
designator SW?, comment ROTARY SWITCH WURTH ELEKTRONIK428527520910
Costo: 1,90; Aggiornato: NO; ContoLavoro: 0
footprint ENCODER_RS3XX
pins: 1, 2, 3 C1, 4, 5 C2, 8

## EVA01 Develer
designator U?
Aggiornato: NO; Costo: 0
footprint EVA01_DevelerBoard
pins: J1_1 +24V, J1_2 +3.3V, J1_3 +5V, J1_4 +1.8V, J1_5 GND, J1_6 RESET, J1_7 PA27, J1_8 PA29, J1_9 PA26, J1_10 PA24, J1_11 PA28, J1_12 PA25, J1_13 GND, J1_14 GND, J1_15 PA23, J1_16 PA22, J1_17 PA21, J1_18 PA20, J1_19 PA19, J1_20 PA18, J1_21 PA17, J1_22 PA16, J1_23 GND, J1_24 GND, J1_25 PA15, J1_26 PA14, J1_27 PA13, J1_28 PA12, J1_29 PA11, J1_30 PA10, J1_31 PA9, J1_32 PA8, J1_33 GND, J1_34 GND, J1_35 PA7, J1_36 PA6, J1_37 PA5, J1_38 PA4, J1_39 PA3, J1_40 PA2, J1_41 PA1, J1_42 PA0, J1_43 GND, J1_44 GND, J1_45 PC27, J1_46 PB18, J1_47 PC28, J1_48 PB19, J1_49 PC29, J1_50 PB20, J1_51 PC30, J1_52 PB23, J7_1 VBAT, J7_2 GND, J7_3 +5V, J7_4 PB1, J7_5 PB3, J7_6 PB14, J7_7 PB24, J7_8 PB15, J7_9 PB10, J7_10 PB22, J7_11 PB5, J7_12 PB25, J7_13 PB4, J7_14 PB11, J7_15 PB28, J7_16 PB21, J7_17 PB31, J7_18 PB27, J7_19 PD8, J7_20 PD9, J7_21 PD12, J7_22 PE31, J7_23 PD11, J7_24 PD10, J7_25 PD29, J7_26 PD13, J7_27 PE29, J7_28 PD28, J7_29 PE30, J7_30 SHDN, J7_31 PD16, J7_32 PD17, J7_33 PB30, J7_34 PD14, J7_35 WKUP, J7_36 JTAGSEL, J7_37 PD26, J7_38 GND, J7_39 PIOBU0_U3, J7_40 HHSDPA, J7_41 PB29, J7_42 HHSDMA, J7_43 RESET, J7_44 GND, J7_45 ADCREF, J7_46 PA31, J7_47 PC2, J7_48 PA30, J7_49 PC0, J7_50 +5V, J7_51 BOOT_RCV, J7_52 +24V, J16_1 +5V, J16_2 GND, J16_3 +3.3V, J16_4 PE28, J16_5 PE15, J16_6 PE17, J16_7 PE25, J16_8 PE11, J16_9 PE24, J16_10 PE13, J16_11 PE7, J16_12 PE9, J16_13 PE14, J16_14 PE6, J16_15 PC25, J16_16 PE12, J16_17 PE5, J16_18 PE27, J16_19 PE1, J16_20 PE2, J16_21 PE3, J16_22 PE4, J16_23 PE8, J16_24 PE26, J16_25 PE16, J16_26 PC26, J16_27 PC23, J16_28 PC21, J16_29 PC24, J16_30 PE0, J16_31 PC19, J16_32 PC31, J16_33 PD25, J16_34 PC4, J16_35 PC20, J16_36 PC19, J16_37 PD22, J16_38 PD24, J16_39 PC3, J16_40 PD21, J16_41 PD23, J16_42 PC22, J16_43 PE10, J16_44 PC1, J16_45 PD27, J16_46 PB26, J16_47 PD20, J16_48 PD15, J16_49 PD31, J16_50 +1.8V, J16_51 PIOBU1, J16_52 GND

## Fermacavo_MMBLC03000
designator Fermacavo?, comment Fermacavo a vite  (mechanical)
Fermacavo MMBLC03000; Costo: 0,0666; Aggiornato: s; ContoLavoro: 1
pins: 1 hidden
1 alternate drawing of the same symbol

## FIDUCIAL
designator FD?
FIDUCIAL, REFERENCE POINT; Aggiornato: S; Costo: 0
footprint ZP_FIDUCIAL
footprint ZP_FIDUCIAL_SMALL
footprint fiducial
pins: 1 FD

## FMMTA92
designator Q?, comment FZT953TA
Aggiornato: NO; Costo: 0
footprint SOT223
pins: 1, 2, 3 (in), 4

## Fori_x_bandelle
designator F?  (no BOM)
Aggiornato: NO; Costo: 0
footprint Fori_x_bandelle
pins: 1 A

## FPF2124_dafare
designator U?
Power Load Switch FPF2124; Aggiornato: SI; Costo: 0,162; Detail: (Rs per >1000pz); ContoLavoro: 0
2 alternate drawings of the same symbol

## FSA4157
designator U?, comment FSA4157P6X_NL
Low Voltage 1R  SPDT Analog Switch, SC70-6, 1.65-5.5v; Aggiornato: NO; Costo: 0
footprint SC70_6L
pins: 1 B1 (io), 2 GND (power), 3 B0 (io), 4 A (io), 5 VCC (power), 6 S (in)

## FSB560A
designator Q?
Costo: 0115; Aggiornato: S; ContoLavoro: 0
footprint SOT-23_UP
pins: 1 B, 2 E, 3 C

## FSB660A
designator Q?
Costo: 0,064; Aggiornato: S; ContoLavoro: 0
footprint SOT-23_UP
pins: 1 B, 2 E, 3 C

## FSUSB42MUX
designator U?
Costo: 0,4; Aggiornato: s; ContoLavoro: 0
footprint MSOP_10 (MSOP 10)
pins: 1 Vcc, 2 Sel, 3 D+, 4 D-, 5 GND, 6 HSD1-, 7 HSD1+, 8 HSD2-, 9 HSD2+, 10 ~{OE}

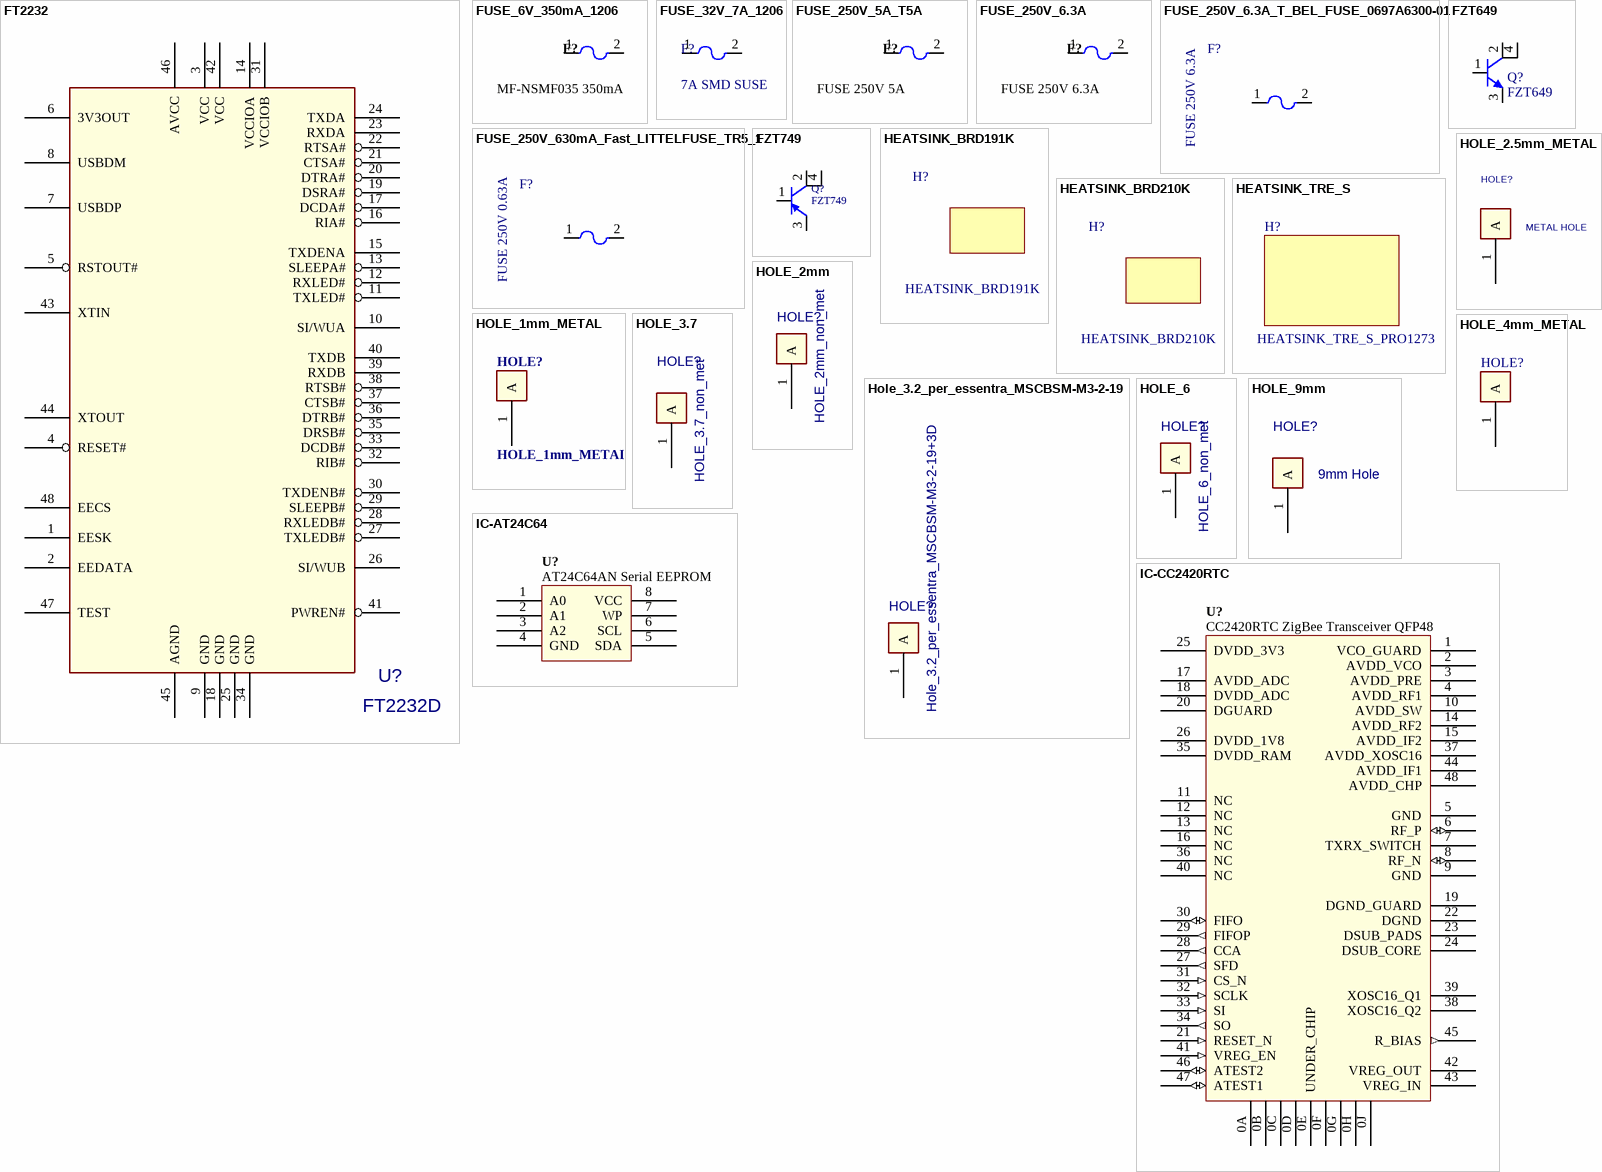
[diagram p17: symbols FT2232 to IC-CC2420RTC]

## FT2232
designator U?, comment FT2232D
Hpcode: ICFT2232D; Costo: 3,5; Aggiornato: s; ContoLavoro: 1
footprint LQFP-48
pins: 1 EESK, 2 EEDATA, 3 VCC, 4 RESET#, 5 RSTOUT#, 6 3V3OUT, 7 USBDP, 8 USBDM, 9 GND, 10 SI/WUA, 11 TXLED#, 12 RXLED#, 13 SLEEPA#, 14 VCCIOA, 15 TXDENA, 16 RIA#, 17 DCDA#, 18 GND, 19 DSRA#, 20 DTRA#, 21 CTSA#, 22 RTSA#, 23 RXDA, 24 TXDA, 25 GND, 26 SI/WUB, 27 TXLEDB#, 28 RXLEDB#, 29 SLEEPB#, 30 TXDENB#, 31 VCCIOB, 32 RIB#, 33 DCDB#, 34 GND, 35 DRSB#, 36 DTRB#, 37 CTSB#, 38 RTSB#, 39 RXDB, 40 TXDB, 41 PWREN#, 42 VCC, 43 XTIN, 44 XTOUT, 45 AGND, 46 AVCC, 47 TEST, 48 EECS

## FUSE_6V_350mA_1206
designator F?, comment MF-NSMF035 350mA
Multifuse, SMD 1206, 350mA; Rated Voltage: 6 V; Aggiornato: NO; Costo: 0
footprint RESC3216
pins: 1, 2

## FUSE_32V_7A_1206
designator F?, comment 7A SMD SUSE
Fuse; Aggiornato: NO; Costo: 0
footprint 1206_UP
pins: 1, 2

## FUSE_250V_5A_T5A
designator F?, comment FUSE 250V 5A
FUSE 250V 5A FUSE T5A TIME DELAY; Costo: 0; Aggiornato: NO
pins: 1, 2

## FUSE_250V_6.3A
designator F?, comment FUSE 250V 6.3A
Costo: 0; Aggiornato: NO
pins: 1, 2

## FUSE_250V_6.3A_T_BEL_FUSE_0697A6300-01
designator F?, comment FUSE 250V 6.3A
FUSE 250Vac 6.3A Time Delay BEL FUSE 0697A6300-01; Costo: 0,26; Aggiornato: S; ContoLavoro: 0
footprint BEL_FUSE_0697A6300-01 (Footprint not found)
pins: 1, 2

## FUSE_250V_630mA_Fast_LITTELFUSE_TR5_1
designator F?, comment FUSE 250V 0.63A
FUSE 250V 0.63A Fast LITTELFUSE TR5; Costo: 0,33; Hpcode: FUSF063A00TE5 da verificare se esiste; Aggiornato: N; ContoLavoro: 0
footprint MICROFUSE 8.5 p5
pins: 1, 2

## FZT649
designator Q?
ZETEX FZT649; Aggiornato: SI; Costo: 0,144; Detail: (Rs per >1000pz); ContoLavoro: 0
simulation model 2N3904 (NPN)
signal-integrity model 2N3904
footprint SOT223
pins: 1 B, 2 C, 3 E, 4 C2

## FZT749
designator Q?
ZETEX FZT749; Aggiornato: SI; Costo: 0,162; Detail: (Rs per >1000pz); ContoLavoro: 0
footprint SOT223
pins: 1 B, 2 C, 3 E, 4 C2
2 alternate drawings of the same symbol

## HEATSINK_BRD191K
designator H?  (mechanical)
Hpcode: MCP115A03ABK; Detail: 1,30€ Costo standard esolver 2018; Aggiornato: S; Costo: 1,30; ContoLavoro: 1
footprint HEATSINK_BRD191K 50x40mm (Footprint not found)

## HEATSINK_BRD210K
designator H?  (mechanical)
Hpcode: MCP123A03; Aggiornato: NO; Costo: 0; ContoLavoro: 1
footprint HEATSINK_BRD210K_MCP123A03_01 (Footprint not found)

## HEATSINK_TRE_S
designator H?, comment HEATSINK_TRE_S_PRO1273
Aggiornato: NO; Costo: 0
footprint HEATSINK_TRES_1273_80mm

## HOLE_1mm_METAL
designator HOLE?  (no BOM)
Aggiornato: NO; Costo: 0
footprint HOLE 1MM
pins: 1 A

## HOLE_2.5mm_METAL
designator HOLE?, comment METAL HOLE
Aggiornato: NO; Costo: 0
footprint HOLE 2.5MM
pins: 1 A

## HOLE_2mm
designator HOLE?, comment HOLE_2mm_non_met  (no BOM)
Aggiornato: NO; Costo: 0
footprint 2MM_HOLE
pins: 1 A

## Hole_3.2_per_essentra_MSCBSM-M3-2-19
designator HOLE?, comment Hole_3.2_per_essentra_MSCBSM-M3-2-19+3D  (no BOM)
Aggiornato: NO; Costo: 0
footprint Hole_3.2_per_essentra_MSCBSM-M3-2-19+3D
footprint Hole_3.2_per_essentra_MSCBSM-M3-2-19
footprint Hole_3.2_per_essentra_MSCBSM-M3-2-19+3D_METALLIZATO
footprint Hole_3.2_per_essentra_MSCBSM-M3-2-19_metallizzato
pins: 1 A

## HOLE_3.7
designator HOLE?, comment HOLE_3.7_non_met  (no BOM)
Aggiornato: NO; Costo: 0
footprint HOLE_3.7_non_met
pins: 1 A

## HOLE_4mm_METAL
designator HOLE?  (no BOM)
Costo: 0; Aggiornato: NO
footprint MTHOLE 4MM
pins: 1 A

## HOLE_6
designator HOLE?, comment HOLE_6_non_met  (no BOM)
Aggiornato: NO; Costo: 0
footprint HOLE_6_non_met
pins: 1 A

## HOLE_9mm
designator HOLE?, comment 9mm Hole  (no BOM)
Aggiornato: NO; Costo: 0
footprint HOLE_9MM
pins: 1 A

## IC-AT24C64
designator U?, comment AT24C64AN Serial EEPROM
AT24C64AN Two-Wire Serial EEPROM 2.7-5.5V SOIC-8 (JEDEC); Bit Width: 1 Bits; Supply Voltage: 2.7 to 5.5 V; Aggiornato: NO; Costo: 0
footprint SOIC8-150-BODY
pins: 1 A0, 2 A1, 3 A2, 4 GND, 5 SDA, 6 SCL, 7 WP, 8 VCC

## IC-CC2420RTC
designator U?, comment CC2420RTC ZigBee Transceiver QFP48
CC2420RTC, 2.45GHz IEEE 802.15.4 (Zigbee) RF Transceiver QFP48; Aggiornato: NO; Costo: 0
footprint SQFP50P700X700-48
pins: 0A, 0B, 0C, 0D, 0E UNDER_CHIP, 0F, 0G, 0H, 0J, 1 VCO_GUARD, 2 AVDD_VCO, 3 AVDD_PRE, 4 AVDD_RF1, 5 GND, 6 RF_P (io), 7 TXRX_SWITCH, 8 RF_N (io), 9 GND, 10 AVDD_SW, 11 NC, 12 NC, 13 NC, 14 AVDD_RF2, 15 AVDD_IF2, 16 NC, 17 AVDD_ADC, 18 DVDD_ADC, 19 DGND_GUARD, 20 DGUARD, 21 RESET_N (in), 22 DGND, 23 DSUB_PADS, 24 DSUB_CORE, 25 DVDD_3V3, 26 DVDD_1V8, 27 SFD (out), 28 CCA (out), 29 FIFOP (out), 30 FIFO (io), 31 CS_N (in), 32 SCLK (in), 33 SI (in), 34 SO (out), 35 DVDD_RAM, 36 NC, 37 AVDD_XOSC16, 38 XOSC16_Q2, 39 XOSC16_Q1, 40 NC, 41 VREG_EN (in), 42 VREG_OUT, 43 VREG_IN, 44 AVDD_IF1, 45 R_BIAS (out), 46 ATEST2 (io), 47 ATEST1 (io), 48 AVDD_CHP

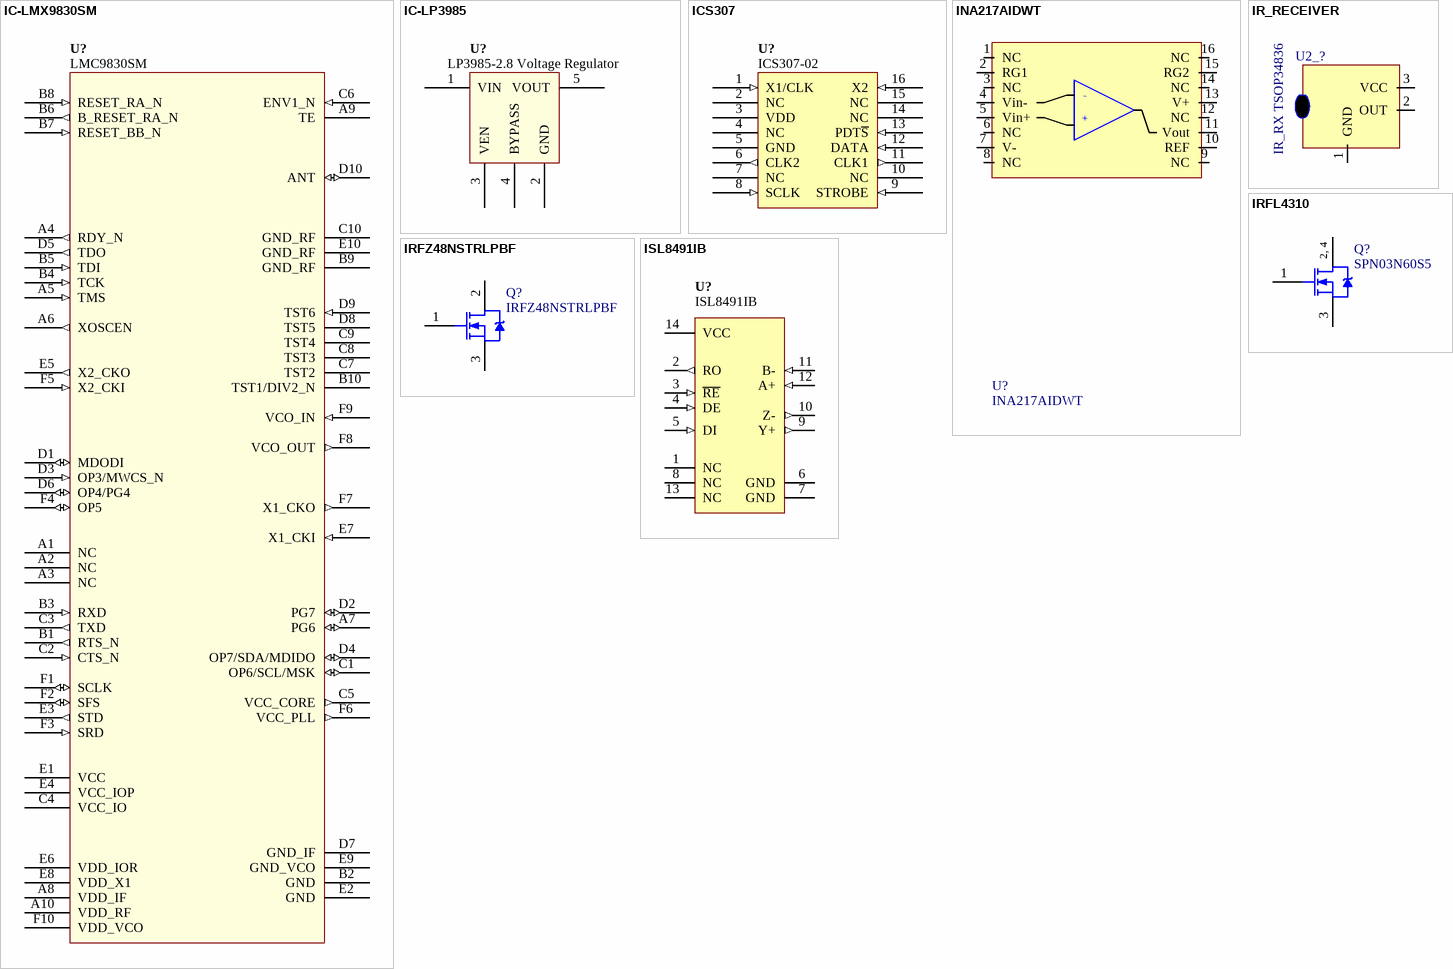
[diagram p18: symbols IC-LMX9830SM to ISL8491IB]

## IC-LMX9830SM
designator U?, comment LMC9830SM
LMC9830SM, 2.45GHz Bluetooth Serial Port Module, BGA60; Aggiornato: NO; Costo: 0
footprint BGA80P9X6-60
pins: A1 NC, A2 NC, A3 NC, A4 RDY_N (out), A5 TMS (in), A6 XOSCEN (out), A7 PG6 (io), A8 VDD_IF, A9 TE, A10 VDD_RF, B1 RTS_N (out), B2 GND (power), B3 RXD (in), B4 TCK (in), B5 TDI (in), B6 B_RESET_RA_N (out), B7 RESET_BB_N (in), B8 RESET_RA_N (in), B9 GND_RF (power), B10 TST1/DIV2_N, C1 OP6/SCL/MSK (io), C2 CTS_N (in), C3 TXD (out), C4 VCC_IO (power), C5 VCC_CORE (out), C6 ENV1_N (in), C7 TST2, C8 TST3, C9 TST4, C10 GND_RF (power), D1 MDODI (io), D2 PG7 (io), D3 OP3/MWCS_N (in), D4 OP7/SDA/MDIDO (io), D5 TDO (out), D6 OP4/PG4 (io), D7 GND_IF (power), D8 TST5, D9 TST6 (in), D10 ANT (io), E1 VCC (power), E2 GND (power), E3 STD (out), E4 VCC_IOP (power), E5 X2_CKO (out), E6 VDD_IOR, E7 X1_CKI (in), E8 VDD_X1, E9 GND_VCO (power), E10 GND_RF (power), F1 SCLK (io), F2 SFS (io), F3 SRD (in), F4 OP5 (io), F5 X2_CKI (in), F6 VCC_PLL (out), F7 X1_CKO (out), F8 VCO_OUT (out), F9 VCO_IN (in), F10 VDD_VCO

## IC-LP3985
designator U?, comment LP3985-2.8 Voltage Regulator
LP3985IM5-2.8, 2V8 Voltage Regulator, Low-Noise Ultra Low-Dropout, 150mA, SOT-23-5; Max Input Voltage: 6 V; Max Output Voltage: 2.803 V; Min Input Voltage: 3.3 V; Min Output Voltage: 2.797 V; Supply Voltage: mV; Aggiornato: NO; Costo: 0
footprint SOT-23-5
pins: 1 VIN, 2 GND, 3 VEN, 4 BYPASS, 5 VOUT

## ICS307
designator U?, comment ICS307-02
ICS307-02, SPI Programmable Clock Generator; Aggiornato: NO; Costo: 0
footprint SOIC127P600-16
pins: 1 X1/CLK (in) "Reference Word Devider Input", 2 NC "Reference Word Devider Input", 3 VDD (power) "Positive Supply, 3V3 or 5V", 4 NC, 5 GND (power), 6 CLK2 (out) "Fixed Clock Ref", 7 NC "Crystal connection", 8 SCLK (in) "Serial Programming Clock", 9 STROBE (in) "Serial Programming Strobe", 10 NC, 11 CLK1 (out) "Variable Clock Output", 12 DATA (in) "Serial Programming Data", 13 PDT~{S} (in) "Low = TriState CLK1 and CLK2 and Power Down", 14 NC, 15 NC, 16 X2 (in) "Crystal Terminal"

## INA217AIDWT
designator U?
Detail: 5,17€ RS >3pz; Aggiornato: s; Costo: 5,17; ContoLavoro: 1
footprint SOIC DW 16
pins: 1 NC, 2 RG1, 3 NC, 4 Vin-, 5 Vin+, 6 NC, 7 V-, 8 NC, 9 NC, 10 REF, 11 Vout, 12 NC, 13 V+, 14 NC, 15 RG2, 16 NC

## IR_RECEIVER
designator U2_?, comment IR_RX TSOP34836
Aggiornato: NO; Costo: 0
footprint IR_RECEIVER_3PIN
pins: 1 GND, 2 OUT, 3 VCC

## IRFL4310
designator Q?, comment SPN03N60S5
HEXFET Power MOSFET; Aggiornato: NO; Costo: 0
footprint SOT-223 (SOT-223/SC-73; 4 Leads; Body 6.7 x 7.3 mm, inc. leads (LxW max))
footprint SOT223
pins: 1 G, 2 D, 3 S, 4 D

## IRFZ48NSTRLPBF
designator Q?
HEXFET MOSFET 55V 64A 14mOhm Codice Mouser: 942-IRFZ48NSTRLPBF; Detail: 1,09 € PER ORDINI MULTIPLI DI 800 PEZZI; Aggiornato: SI; Costo: 1,09 €; ContoLavoro: 0
footprint D2PAK3
pins: 1 G, 2 D, 3 S

## ISL8491IB
designator U?
ISL8491IB, RS-485/RS-422 Transceivers; Aggiornato: NO; Costo: 0
footprint SOIC127P600-14N
pins: 1 NC, 2 RO (out), 3 ~{RE} (in), 4 DE (in), 5 DI (in), 6 GND (power), 7 GND (power), 8 NC, 9 Y+ (out), 10 Z- (out), 11 B- (in), 12 A+ (in), 13 NC, 14 VCC (power)

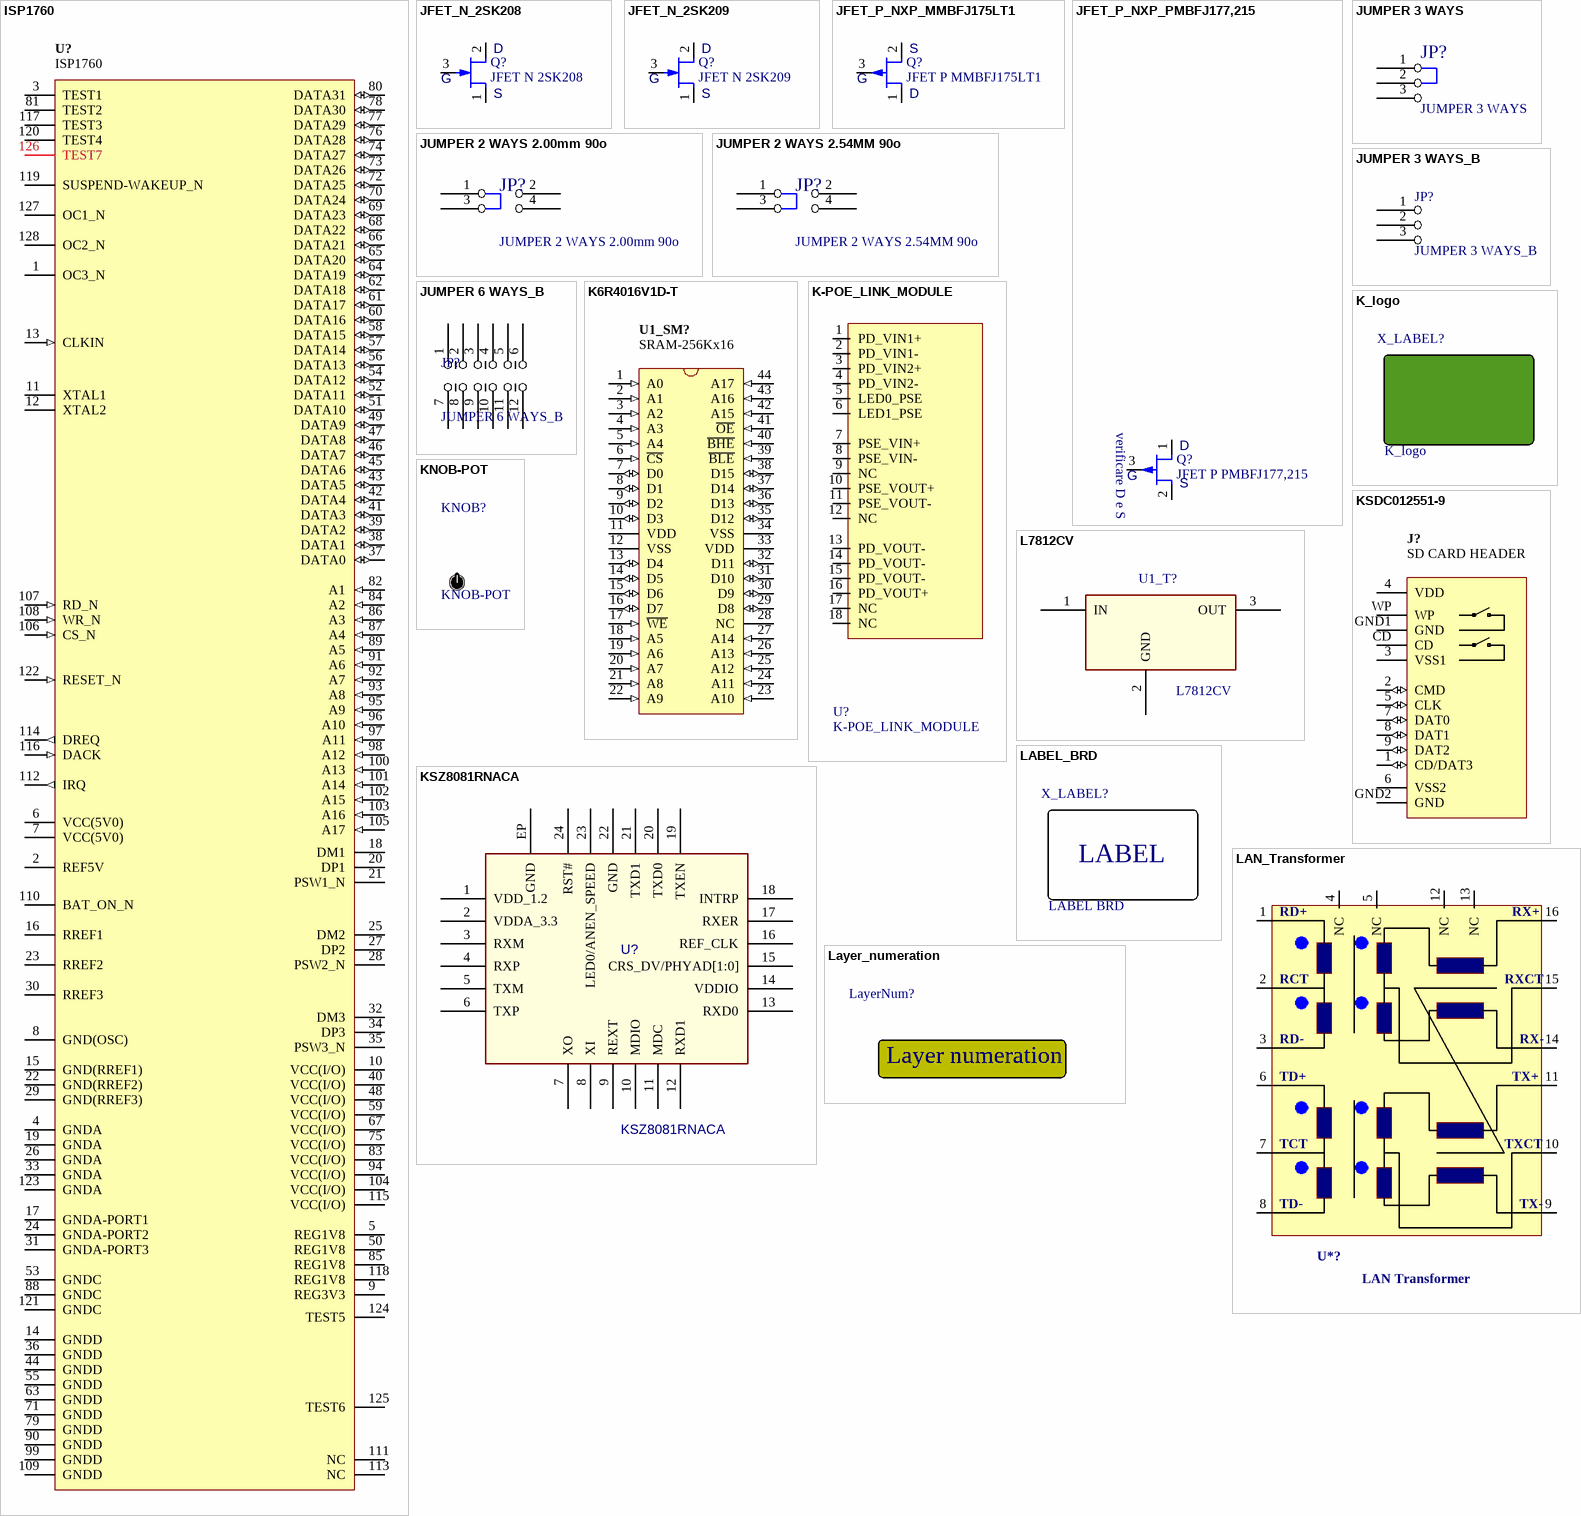
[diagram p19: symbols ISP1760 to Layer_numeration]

## ISP1760
designator U?
Hi-Speed Universal Serial Bus host controller; Aggiornato: NO; Costo: 0
footprint SOT425-1
pins: 1 OC3_N "wake-up input; when not in use, connect this pin to ground through a 10 k resistor; input pad; TTL; 5 V tolerant", 2 REF5V "wake-up input; when not in use, connect this pin to ground through a 10 k resistor; input pad; TTL; 5 V tolerant", 3 TEST1 "wake-up input; when not in use, connect this pin to ground through a 10 k resistor; input pad; TTL; 5 V tolerant", 4 GNDA (power) "digital ground", 5 REG1V8 (power) "supply voltage (3.3 V ?0.3 V); this pin supplies the internal voltage regulator and the analog circuit", 6 VCC(5V0) (power) "supply voltage; used to supply voltage to the I/O pads", 7 VCC(5V0) (power) "supply voltage; used to supply voltage to the I/O pads", 8 GND(OSC) (power) "digital ground", 9 REG3V3 (power) "supply voltage (3.3 V ?0.3 V); this pin supplies the internal voltage regulator and the analog circuit", 10 VCC(I/O) (power) "supply voltage; used to supply voltage to the I/O pads", 11 XTAL1 "wake-up input; when not in use, connect this pin to ground through a 10 k resistor; input pad; TTL; 5 V tolerant", 12 XTAL2 "wake-up input; when not in use, connect this pin to ground through a 10 k resistor; input pad; TTL; 5 V tolerant", 13 CLKIN (in) "DMA write strobe input (programmable polarity); when not in use, connect this pin to VCC(I/O) through a 10 k resistor; TTL; 5 V tolerant", 14 GNDD (power) "digital ground", 15 GND(RREF1) (power) "digital ground", 16 RREF1 "wake-up input; when not in use, connect this pin to ground through a 10 k resistor; input pad; TTL; 5 V tolerant", 17 GNDA-PORT1 (power) "digital ground", 18 DM1, 19 GNDA (power) "digital ground", 20 DP1, 21 PSW1_N "wake-up input; when not in use, connect this pin to ground through a 10 k resistor; input pad; TTL; 5 V tolerant", 22 GND(RREF2) (power) "digital ground", 23 RREF2 "wake-up input; when not in use, connect this pin to ground through a 10 k resistor; input pad; TTL; 5 V tolerant", 24 GNDA-PORT2 (power) "digital ground", 25 DM2, 26 GNDA (power) "digital ground", 27 DP2, 28 PSW2_N "wake-up input; when not in use, connect this pin to ground through a 10 k resistor; input pad; TTL; 5 V tolerant", 29 GND(RREF3) (power) "digital ground", 30 RREF3 "wake-up input; when not in use, connect this pin to ground through a 10 k resistor; input pad; TTL; 5 V tolerant", 31 GNDA-PORT3 (power) "digital ground", 32 DM3, 33 GNDA (power) "digital ground", 34 DP3, 35 PSW3_N "wake-up input; when not in use, connect this pin to ground through a 10 k resistor; input pad; TTL; 5 V tolerant", 36 GNDD (power) "digital ground", 37 DATA0 (io), 38 DATA1 (io), 39 DATA2 (io), 40 VCC(I/O) (power) "regulator output voltage (1.8 V ?0.15 V); decouple this pin using a 0.1 mF capacitor", 41 DATA3 (io), 42 DATA4 (io), 43 DATA5 (io), 44 GNDD (power) "digital ground", 45 DATA6 (io), 46 DATA7 (io), 47 DATA8 (io), 48 VCC(I/O) (power) "regulator output voltage (1.8 V ?0.15 V); decouple this pin using 4.7 mF and 0.1 mF capacitors", 49 DATA9 (io), 50 REG1V8 (power) "supply voltage (3.3 V ?0.3 V); this pin supplies the internal voltage regulator and the analog circuit", 51 DATA10 (io), 52 DATA11 (io), 53 GNDC (power) "digital ground", 54 DATA12 (io), 55 GNDD (power) "digital ground", 56 DATA13 (io), 57 DATA14 (io), 58 DATA15 (io), 59 VCC(I/O) (power) "supply voltage (3.3 V ?0.3 V); this pin supplies the internal voltage regulator and the analog circuit", 60 DATA16 (io), 61 DATA17 (io), 62 DATA18 (io), 63 GNDD (power) "digital ground", 64 DATA19 (io), 65 DATA20 (io), 66 DATA21 (io), 67 VCC(I/O) (power) "supply voltage (3.3 V ?0.3 V); this pin supplies the internal voltage regulator and the analog circuit", 68 DATA22 (io), 69 DATA23 (io), 70 DATA24 (io), 71 GNDD (power) "digital ground", 72 DATA25 (io), 73 DATA26 (io), 74 DATA27 (io), 75 VCC(I/O) (power) "supply voltage; used to supply voltage to the I/O pads", 76 DATA28 (io), 77 DATA29 (io), 78 DATA30 (io), 79 GNDD (power) "digital ground", 80 DATA31 (io), 81 TEST2 "wake-up input; when not in use, connect this pin to ground through a 10 k resistor; input pad; TTL; 5 V tolerant", 82 A1 (in) "bit 0 of the address bus; input pad; TTL; 5 V tolerant", 83 VCC(I/O) (power) "supply voltage; used to supply voltage to the I/O pads", 84 A2 (in) "bit 1 of the address bus; input pad; TTL; 5 V tolerant", 85 REG1V8 (power) "regulator output voltage (1.8 V ?0.15 V); decouple this pin using 4.7 mF and 0.1 mF capacitors", 86 A3 (in) "bit 2 of the address bus; input pad; TTL; 5 V tolerant", 87 A4 (in) "bit 3 of the address bus; input pad; TTL; 5 V tolerant", 88 GNDC (power) "digital ground", 89 A5 (in) "bit 4 of the address bus; input pad; TTL; 5 V tolerant", 90 GNDD (power) "digital ground", 91 A6 (in) "bit 5 of the address bus; input pad; TTL; 5 V tolerant", 92 A7 (in) "bit 6 of the address bus; input pad; TTL; 5 V tolerant", 93 A8 (in) "bit 7 of the address bus; input pad; TTL; 5 V tolerant", 94 VCC(I/O) (power) "supply voltage; used to supply voltage to the I/O pads", 95 A9 (in) "bit 0 of the address bus; input pad; TTL; 5 V tolerant", 96 A10 (in) "bit 1 of the address bus; input pad; TTL; 5 V tolerant", 97 A11 (in) "bit 2 of the address bus; input pad; TTL; 5 V tolerant", 98 A12 (in) "bit 3 of the address bus; input pad; TTL; 5 V tolerant", 99 GNDD (power) "digital ground", 100 A13 (in) "bit 4 of the address bus; input pad; TTL; 5 V tolerant", 101 A14 (in) "bit 5 of the address bus; input pad; TTL; 5 V tolerant", 102 A15 (in) "bit 6 of the address bus; input pad; TTL; 5 V tolerant", 103 A16 (in) "bit 7 of the address bus; input pad; TTL; 5 V tolerant", 104 VCC(I/O) (power) "regulator output voltage (1.8 V ?0.15 V); decouple this pin using a 0.1 mF capacitor", 105 A17 (in) "bit 5 of the address bus; input pad; TTL; 5 V tolerant", 106 CS_N (in) "DMA write strobe input (programmable polarity); when not in use, connect this pin to VCC(I/O) through a 10 k resistor; TTL; 5 V tolerant", 107 RD_N (in) "DMA write strobe input (programmable polarity); when not in use, connect this pin to VCC(I/O) through a 10 k resistor; TTL; 5 V tolerant", 108 WR_N (in) "DMA write strobe input (programmable polarity); when not in use, connect this pin to VCC(I/O) through a 10 k resistor; TTL; 5 V tolerant", 109 GNDD (power) "digital ground", 110 BAT_ON_N "wake-up input; when not in use, connect this pin to ground through a 10 k resistor; input pad; TTL; 5 V tolerant", 111 NC "wake-up input; when not in use, connect this pin to ground through a 10 k resistor; input pad; TTL; 5 V tolerant", 112 IRQ (out) "DMA request (programmable polarity) output; when not in use, connect this pin to ground through a 10 k resistor", 113 NC "wake-up input; when not in use, connect this pin to ground through a 10 k resistor; input pad; TTL; 5 V tolerant", 114 DREQ (out) "DMA request (programmable polarity) output; when not in use, connect this pin to ground through a 10 k resistor", 115 VCC(I/O) (power) "regulator output voltage (1.8 V ?0.15 V); decouple this pin using 4.7 mF and 0.1 mF capacitors", 116 DACK (in) "DMA write strobe input (programmable polarity); when not in use, connect this pin to VCC(I/O) through a 10 k resistor; TTL; 5 V tolerant", 117 TEST3 "wake-up input; when not in use, connect this pin to ground through a 10 k resistor; input pad; TTL; 5 V tolerant", 118 REG1V8 (power) "supply voltage (3.3 V ?0.3 V); this pin supplies the internal voltage regulator and the analog circuit", 119 SUSPEND-WAKEUP_N "wake-up input; when not in use, connect this pin to ground through a 10 k resistor; input pad; TTL; 5 V tolerant", 120 TEST4 "wake-up input; when not in use, connect this pin to ground through a 10 k resistor; input pad; TTL; 5 V tolerant", 121 GNDC (power) "digital ground", 122 RESET_N (in) "DMA write strobe input (programmable polarity); when not in use, connect this pin to VCC(I/O) through a 10 k resistor; TTL; 5 V tolerant", 123 GNDA (power) "digital ground", 124 TEST5 "wake-up input; when not in use, connect this pin to ground through a 10 k resistor; input pad; TTL; 5 V tolerant", 125 TEST6 "wake-up input; when not in use, connect this pin to ground through a 10 k resistor; input pad; TTL; 5 V tolerant", 126 TEST7 "wake-up input; when not in use, connect this pin to ground through a 10 k resistor; input pad; TTL; 5 V tolerant", 127 OC1_N "wake-up input; when not in use, connect this pin to ground through a 10 k resistor; input pad; TTL; 5 V tolerant", 128 OC2_N "wake-up input; when not in use, connect this pin to ground through a 10 k resistor; input pad; TTL; 5 V tolerant"

## JFET_N_2SK208
designator Q?, comment JFET N 2SK208
JFET N channel 2SK208; Costo: 0,32; ContoLavoro: 0; Aggiornato: s
footprint SOT-23_UP
footprint SOT-23_MINIMAL
pins: 1 SOURCE, 2 DRAIN, 3 GATE

## JFET_N_2SK209
designator Q?, comment JFET N 2SK209
JFET N channel 2SK209; Costo: 0,34; ContoLavoro: 0; Aggiornato: s
footprint SOT-23_UP
footprint SOT-23_MINIMAL
pins: 1 SOURCE, 2 DRAIN, 3 GATE

## JFET_P_NXP_MMBFJ175LT1
designator Q?, comment JFET P MMBFJ175LT1
JFET p channel NXP MMBFJ175LT1; Costo: 0,15; ContoLavoro: 0
footprint SOT-23_UP
footprint SOT-23_MINIMAL (SOT-23_MINIMAL Corretto e verificato)
pins: 1 DRAIN, 2 SOURCE, 3 GATE

## JFET_P_NXP_PMBFJ177,215
designator Q?, comment JFET P PMBFJ177,215
JFET p channel NXP PMBFJ177,215; Costo: 0,148; ContoLavoro: 0
footprint SOT-23_UP
footprint SOT-23_MINIMAL (SOT-23_MINIMAL Corretto e verificato)
pins: 1 DRAIN, 2 SOURCE, 3 GATE

## JUMPER 2 WAYS 2.00mm 90o
designator JP?
Detail: 1/12 0,43€ (RS PER >250pz) DEL CONNETTORE DA 36 PIN; Aggiornato: SI; Costo: 0,036 da verificare; ContoLavoro: 0
footprint 2X2X2mm_PIN STRIPES 90o
pins: 1, 2, 3, 4

## JUMPER 2 WAYS 2.54MM 90o
designator JP?
Detail: 1/12 0,43€ (RS PER >250pz) DEL CONNETTORE DA 36 PIN; Aggiornato: SI; Costo: 0,036 da verificare; ContoLavoro: 0
footprint 2X2X2.54_PIN STRIPES 90o
pins: 1, 2, 3, 4

## JUMPER 3 WAYS
designator JP?
Detail: 1/12 0,43€ (RS PER >250pz) DEL CONNETTORE DA 36 PIN; Aggiornato: SI; Costo: 0,036; ContoLavoro: 0
footprint JUMPER 2.54\3
pins: 1, 2, 3

## JUMPER 3 WAYS_B
designator JP?
Costo: 0; Aggiornato: NO
footprint JUMPER 2.54\3
pins: 1, 2, 3

## JUMPER 6 WAYS_B
designator JP?
Costo: 0; Aggiornato: NO
footprint JUMPER 12X2.54
pins: 1, 2, 3, 4, 5, 6, 7, 8, 9, 10, 11, 12

## K6R4016V1D-T
designator U1_SM?, comment SRAM-256Kx16
K6R4016V1D-TC10T, 256K x 16-Bit SRAM, TSOP44; Bit Width: 16 Bits; Supply Voltage: 3.3 V; Aggiornato: NO; Costo: 0
footprint TSOP80P1176-44
pins: 1 A0 (in), 2 A1 (in), 3 A2 (in), 4 A3 (in), 5 A4 (in), 6 ~{CS} (in), 7 D0 (io), 8 D1 (io), 9 D2 (io), 10 D3 (io), 11 VDD (power), 12 VSS (power), 13 D4 (io), 14 D5 (io), 15 D6 (io), 16 D7 (io), 17 ~{WE} (in), 18 A5 (in), 19 A6 (in), 20 A7 (in), 21 A8 (in), 22 A9 (in), 23 A10 (in), 24 A11 (in), 25 A12 (in), 26 A13 (in), 27 A14 (in), 28 NC, 29 D8 (io), 30 D9 (io), 31 D10 (io), 32 D11 (io), 33 VDD (power), 34 VSS (power), 35 D12 (io), 36 D13 (io), 37 D14 (io), 38 D15 (io), 39 ~{BLE} (in), 40 ~{BHE} (in), 41 ~{OE} (in), 42 A15 (in), 43 A16 (in), 44 A17 (in)
1 alternate drawing of the same symbol

## K-POE_LINK_MODULE
designator U?
Aggiornato: n; Costo: 30; ContoLavoro: 0
footprint K-POE_LINK_MODULE (POE-LINK-beta)
footprint K-POE_COMPATIBILE_SILVERTEL (POE-LINK-beta)
pins: 1 PD_VIN1+, 2 PD_VIN1-, 3 PD_VIN2+, 4 PD_VIN2-, 5 LED0_PSE, 6 LED1_PSE, 7 PSE_VIN+, 8 PSE_VIN-, 9 NC, 10 PSE_VOUT+, 11 PSE_VOUT-, 12 NC, 13 PD_VOUT-, 14 PD_VOUT-, 15 PD_VOUT-, 16 PD_VOUT+, 17 NC, 18 NC

## K_logo
designator X_LABEL?
Costo: 0; Aggiornato: NO
footprint K_logo_1mmx1mm (LOGO K-array 1mmx1mm)
footprint K_logo_7mmx5mm (LOGO K-array 7mmx5mm)
footprint K_logo_10mmx7mm (LOGO K-array 10mmx7mm)
footprint K_logo_12mmx9mm (LOGO K-array 12mmx9mm)
footprint K_logo_25mmx18mm (LOGO K-array 25mmx18mm)

## KNOB-POT
designator KNOB?  (mechanical)
Manopola potenziometro KNOB-POT; Costo: 0,04; Aggiornato: s; ContoLavoro: 1
pins: 1 hidden
1 alternate drawing of the same symbol

## KSDC012551-9
designator J?, comment SD CARD HEADER
Secure Digital Card Socket; Max Current: mA; Aggiornato: NO; Costo: 0
footprint KSDC012551
pins: 1 CD/DAT3 (io), 2 CMD (io), 3 VSS1 (power), 4 VDD (power), 5 CLK (io), 6 VSS2 (power), 7 DAT0 (io), 8 DAT1 (io), 9 DAT2 (io), CD (oc), GND1 GND (power), GND2 GND (power), WP (oc)

## KSZ8081RNACA
designator U?
KSZ8081RNACA PHY; Aggiornato: NO; Costo: 1; ContoLavoro: 0
footprint QFN-25_KSZ8081RN
pins: 1 VDD_1.2, 2 VDDA_3.3, 3 RXM, 4 RXP, 5 TXM, 6 TXP, 7 XO, 8 XI, 9 REXT, 10 MDIO, 11 MDC, 12 RXD1, 13 RXD0, 14 VDDIO, 15 CRS_DV/PHYAD[1:0], 16 REF_CLK, 17 RXER, 18 INTRP, 19 TXEN, 20 TXD0, 21 TXD1, 22 GND, 23 LED0/ANEN_SPEED, 24 RST#, EP GND

## L7812CV
designator U1_T?
Costo: 0; DeviceFunction: Voltage Regulator; Aggiornato: NO
footprint TO220_123
pins: 1 IN, 2 GND, 3 OUT

## LABEL_BRD
designator X_LABEL?, comment LABEL BRD
Costo: 0,01; HPcode: Bxxxxxfannn; Aggiornato: s; ContoLavoro: 2
footprint LABEL 25X8
footprint LABEL_25X8+LayerNum+StackStripes_4layers
footprint LABEL_25X8+LayerNum_4layers
footprint LABEL 30X10
footprint LABEL 25X6
footprint LABEL 25X5

## LAN_Transformer
designator U*?, comment LAN Transformer
Aggiornato: NO; Costo: 0
footprint Model Name (Footprint not found)
pins: 1, 2, 3, 4 NC, 5 NC, 6, 7, 8, 9, 10, 11, 12 NC, 13 NC, 14, 15, 16

## Layer_numeration
designator LayerNum?  (value not drawn)  (no BOM)
Costo: 0; Aggiornato: s
footprint Layer_numeration_4layers

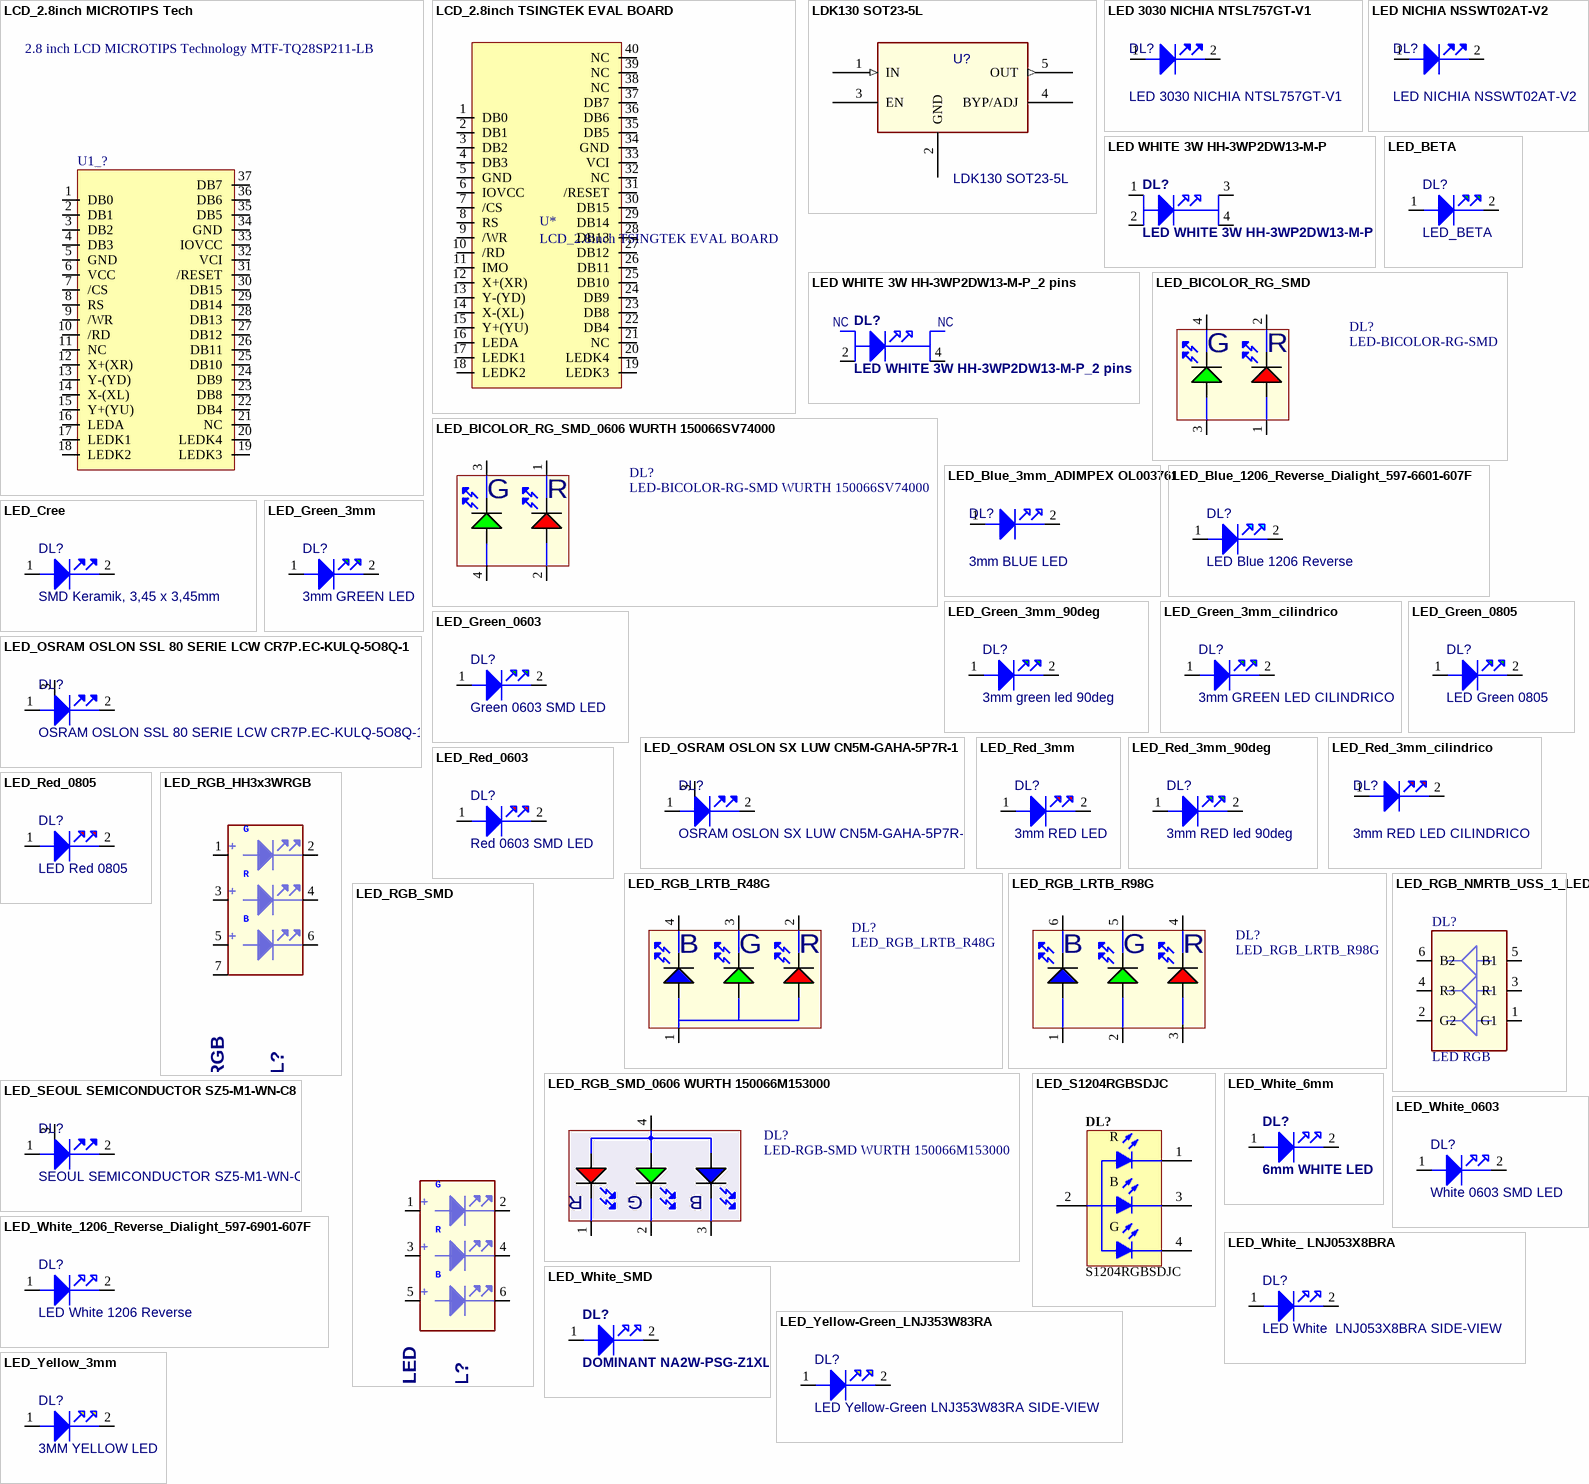
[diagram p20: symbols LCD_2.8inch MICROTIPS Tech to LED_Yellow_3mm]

## LCD_2.8inch MICROTIPS Tech
designator U1_?, comment 2.8 inch LCD MICROTIPS Technology MTF-TQ28SP211-LB
Aggiornato: NO; Costo: 0
footprint TFT MICROTIPS MTF-TQ28SP211-LB
pins: 1 DB0, 2 DB1, 3 DB2, 4 DB3, 5 GND, 6 VCC, 7 /CS, 8 RS, 9 /WR, 10 /RD, 11 NC, 12 X+(XR), 13 Y-(YD), 14 X-(XL), 15 Y+(YU), 16 LEDA, 17 LEDK1, 18 LEDK2, 19 LEDK3, 20 LEDK4, 21 NC, 22 DB4, 23 DB8, 24 DB9, 25 DB10, 26 DB11, 27 DB12, 28 DB13, 29 DB14, 30 DB15, 31 /RESET, 32 VCI, 33 IOVCC, 34 GND, 35 DB5, 36 DB6, 37 DB7

## LCD_2.8inch TSINGTEK EVAL BOARD
designator U*
Costo: 0
footprint Model Name (Footprint not found)
footprint HEADER PBD-40 2X20_FEMALE
pins: 1 DB0, 2 DB1, 3 DB2, 4 DB3, 5 GND, 6 IOVCC, 7 /CS, 8 RS, 9 /WR, 10 /RD, 11 IMO, 12 X+(XR), 13 Y-(YD), 14 X-(XL), 15 Y+(YU), 16 LEDA, 17 LEDK1, 18 LEDK2, 19 LEDK3, 20 LEDK4, 21 NC, 22 DB4, 23 DB8, 24 DB9, 25 DB10, 26 DB11, 27 DB12, 28 DB13, 29 DB14, 30 DB15, 31 /RESET, 32 NC, 33 VCI, 34 GND, 35 DB5, 36 DB6, 37 DB7, 38 NC, 39 NC, 40 NC

## LDK130 SOT23-5L
designator U?
Costo: 0; DeviceFunction: Voltage Regulator; Aggiornato: NO
footprint SOT-23 5PIN
pins: 1 IN (in), 2 GND, 3 EN, 4 BYP/ADJ, 5 OUT (out)

## LED 3030 NICHIA NTSL757GT-V1
designator DL?
NICHIA NTSL757GT-V1; Detail: Morandi Welt Electronic; Costo: 0,060; Aggiornato: si; ContoLavoro: 1
footprint LED_3030_NICHIA NTSL757GT-V1
pins: 1 ANODE, 2 CATHODE

## LED NICHIA NSSWT02AT-V2
designator DL?
Detail: Morandi Welt Electronic; Costo: 0,060; Aggiornato: si; ContoLavoro: 1
footprint LED_NICHIA_NSSWT02AT-V2 (Footprint led Nichia NSSWT02AT-V2)
pins: 1 ANODE, 2 CATHODE

## LED WHITE 3W HH-3WP2DW13-M-P
designator DL?
Costo: 0; Aggiornato: SI
footprint LED WHITE HH-3WP2DW13-M-P DISSIP
pins: 1 ANODE, 2 ANODE, 3 CATHODE, 4 CATHODE

## LED WHITE 3W HH-3WP2DW13-M-P_2 pins
designator DL?
Costo: 0; Aggiornato: SI
footprint LED WHITE HH-3WP2DW13-M-P DISSIP_2pins
pins: 2 ANODE, 4 CATHODE

## LED_BETA
designator DL?
SizeCode: 1206; Aggiornato: n; ContoLavoro: 0
footprint 1206_REVERSE_LED_Dialight
pins: 1 ANODE, 2 CATHODE

## LED_BICOLOR_RG_SMD
designator DL?, comment LED-BICOLOR-RG-SMD
KPTB-1615ESGC; Aggiornato: NO; ContoLavoro: 0
footprint LED_RG_1615 (LED BICOLOR R/G 1.6x1.5)
pins: 1 AN, 2 R_CAT, 3 G_CAT, 4 B_CAT

## LED_BICOLOR_RG_SMD_0606 WURTH 150066SV74000
designator DL?, comment LED-BICOLOR-RG-SMD WURTH 150066SV74000
Costo: 0,065; Aggiornato: S; ContoLavoro: 0
footprint LED_RG_0606 (LED BICOLOR R/G 1.6x1.6)
pins: 1 AN, 2 R_CAT, 3 G_CAT, 4 B_CAT

## LED_Blue_3mm_ADIMPEX OL003761
designator DL?, comment 3mm BLUE LED
LED 3mm BLUE LED; Costo: 0; SizeCode: Dia. 3mm; Aggiornato: s
footprint 3MM LED
footprint 3mm LED-DIST16mm (Footprint not found)
footprint 3mm LED-DIST22mm (Footprint not found)
pins: 1 ANODE, 2 CATHODE

## LED_Blue_1206_Reverse_Dialight_597-6601-607F
designator DL?, comment LED Blue 1206 Reverse
LED 597-6601-607F; Detail: € Farnell Pz>100; Costo: 0,34; SizeCode: 1206; Aggiornato: n; ContoLavoro: 0
footprint 1206_REVERSE_LED_Dialight_Blue (Footprint not found)
pins: 1 ANODE, 2 CATHODE

## LED_Cree
designator DL?, comment SMD Keramik, 3,45 x 3,45mm
LED Cree; Costo: 0; Aggiornato: NO
footprint Cree XP-G R4
pins: 1 ANODE, 2 CATHODE

## LED_Green_3mm
designator DL?, comment 3mm GREEN LED
LED Green 3mm; Costo: 0,10; SizeCode: Dia. 3mm; Aggiornato: s; ContoLavoro: 0
footprint 3MM LED
footprint 3mm LED-DIST16mm (Footprint not found)
footprint 3mm LED-DIST22mm (Footprint not found)
pins: 1 ANODE, 2 CATHODE

## LED_Green_3mm_90deg
designator DL?, comment 3mm green led 90deg
LED Green 3mm 90deg; Costo: 0,3; Aggiornato: s; ContoLavoro: 0
footprint 3MM GRN LED 90deg H5
pins: 1 ANODE, 2 CATHODE

## LED_Green_3mm_cilindrico
designator DL?, comment 3mm GREEN LED CILINDRICO
LED Green 3mm CILINDRICO; Hpcode: LED3GRE001; Costo: 0,10; SizeCode: Dia. 3mm; Aggiornato: s; ContoLavoro: 0
footprint 3MM CILINDRIC GRN LED-DIST14mm
footprint 3MM CILINDRIC GRN LED-DIST20mm
footprint 3MM CILINDRIC GRN LED
pins: 1 ANODE, 2 CATHODE

## LED_Green_0603
designator DL?, comment Green 0603 SMD LED
LED Green 0603; Costo: 0,08; SizeCode: 0603; Aggiornato: S; ContoLavoro: 0
footprint 0603N_LED
pins: 1 ANODE, 2 CATHODE

## LED_Green_0805
designator DL?, comment LED Green 0805
Costo: 0,06; Aggiornato: S; ContoLavoro: 0
footprint LED_0805
pins: 1 ANODE, 2 CATHODE

## LED_OSRAM OSLON SSL 80 SERIE LCW CR7P.EC-KULQ-5O8Q-1
designator DL?, comment OSRAM OSLON SSL 80 SERIE LCW CR7P.EC-KULQ-5O8Q-1
Costo: 0,702; Aggiornato: si; ContoLavoro: 1
footprint LED_OSRAM OSLON SSL 80
pins: 1 ANODE, 2 CATHODE, 3 HEATER

## LED_OSRAM OSLON SX LUW CN5M-GAHA-5P7R-1
designator DL?, comment OSRAM OSLON SX LUW CN5M-GAHA-5P7R-1
Costo: 0,875; Aggiornato: si; ContoLavoro: 0
footprint LED_OSRAM OSLON SX LUW CN5M
pins: 1 ANODE, 2 CATHODE, 3 HEATER

## LED_Red_3mm
designator DL?, comment 3mm RED LED
LED Red 3mm; Costo: 0,10; SizeCode: Dia. 3mm; Aggiornato: s; ContoLavoro: 0
footprint 3MM LED
footprint 3mm LED-DIST16mm (Footprint not found)
footprint 3mm LED-DIST22mm (Footprint not found)
pins: 1 ANODE, 2 CATHODE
